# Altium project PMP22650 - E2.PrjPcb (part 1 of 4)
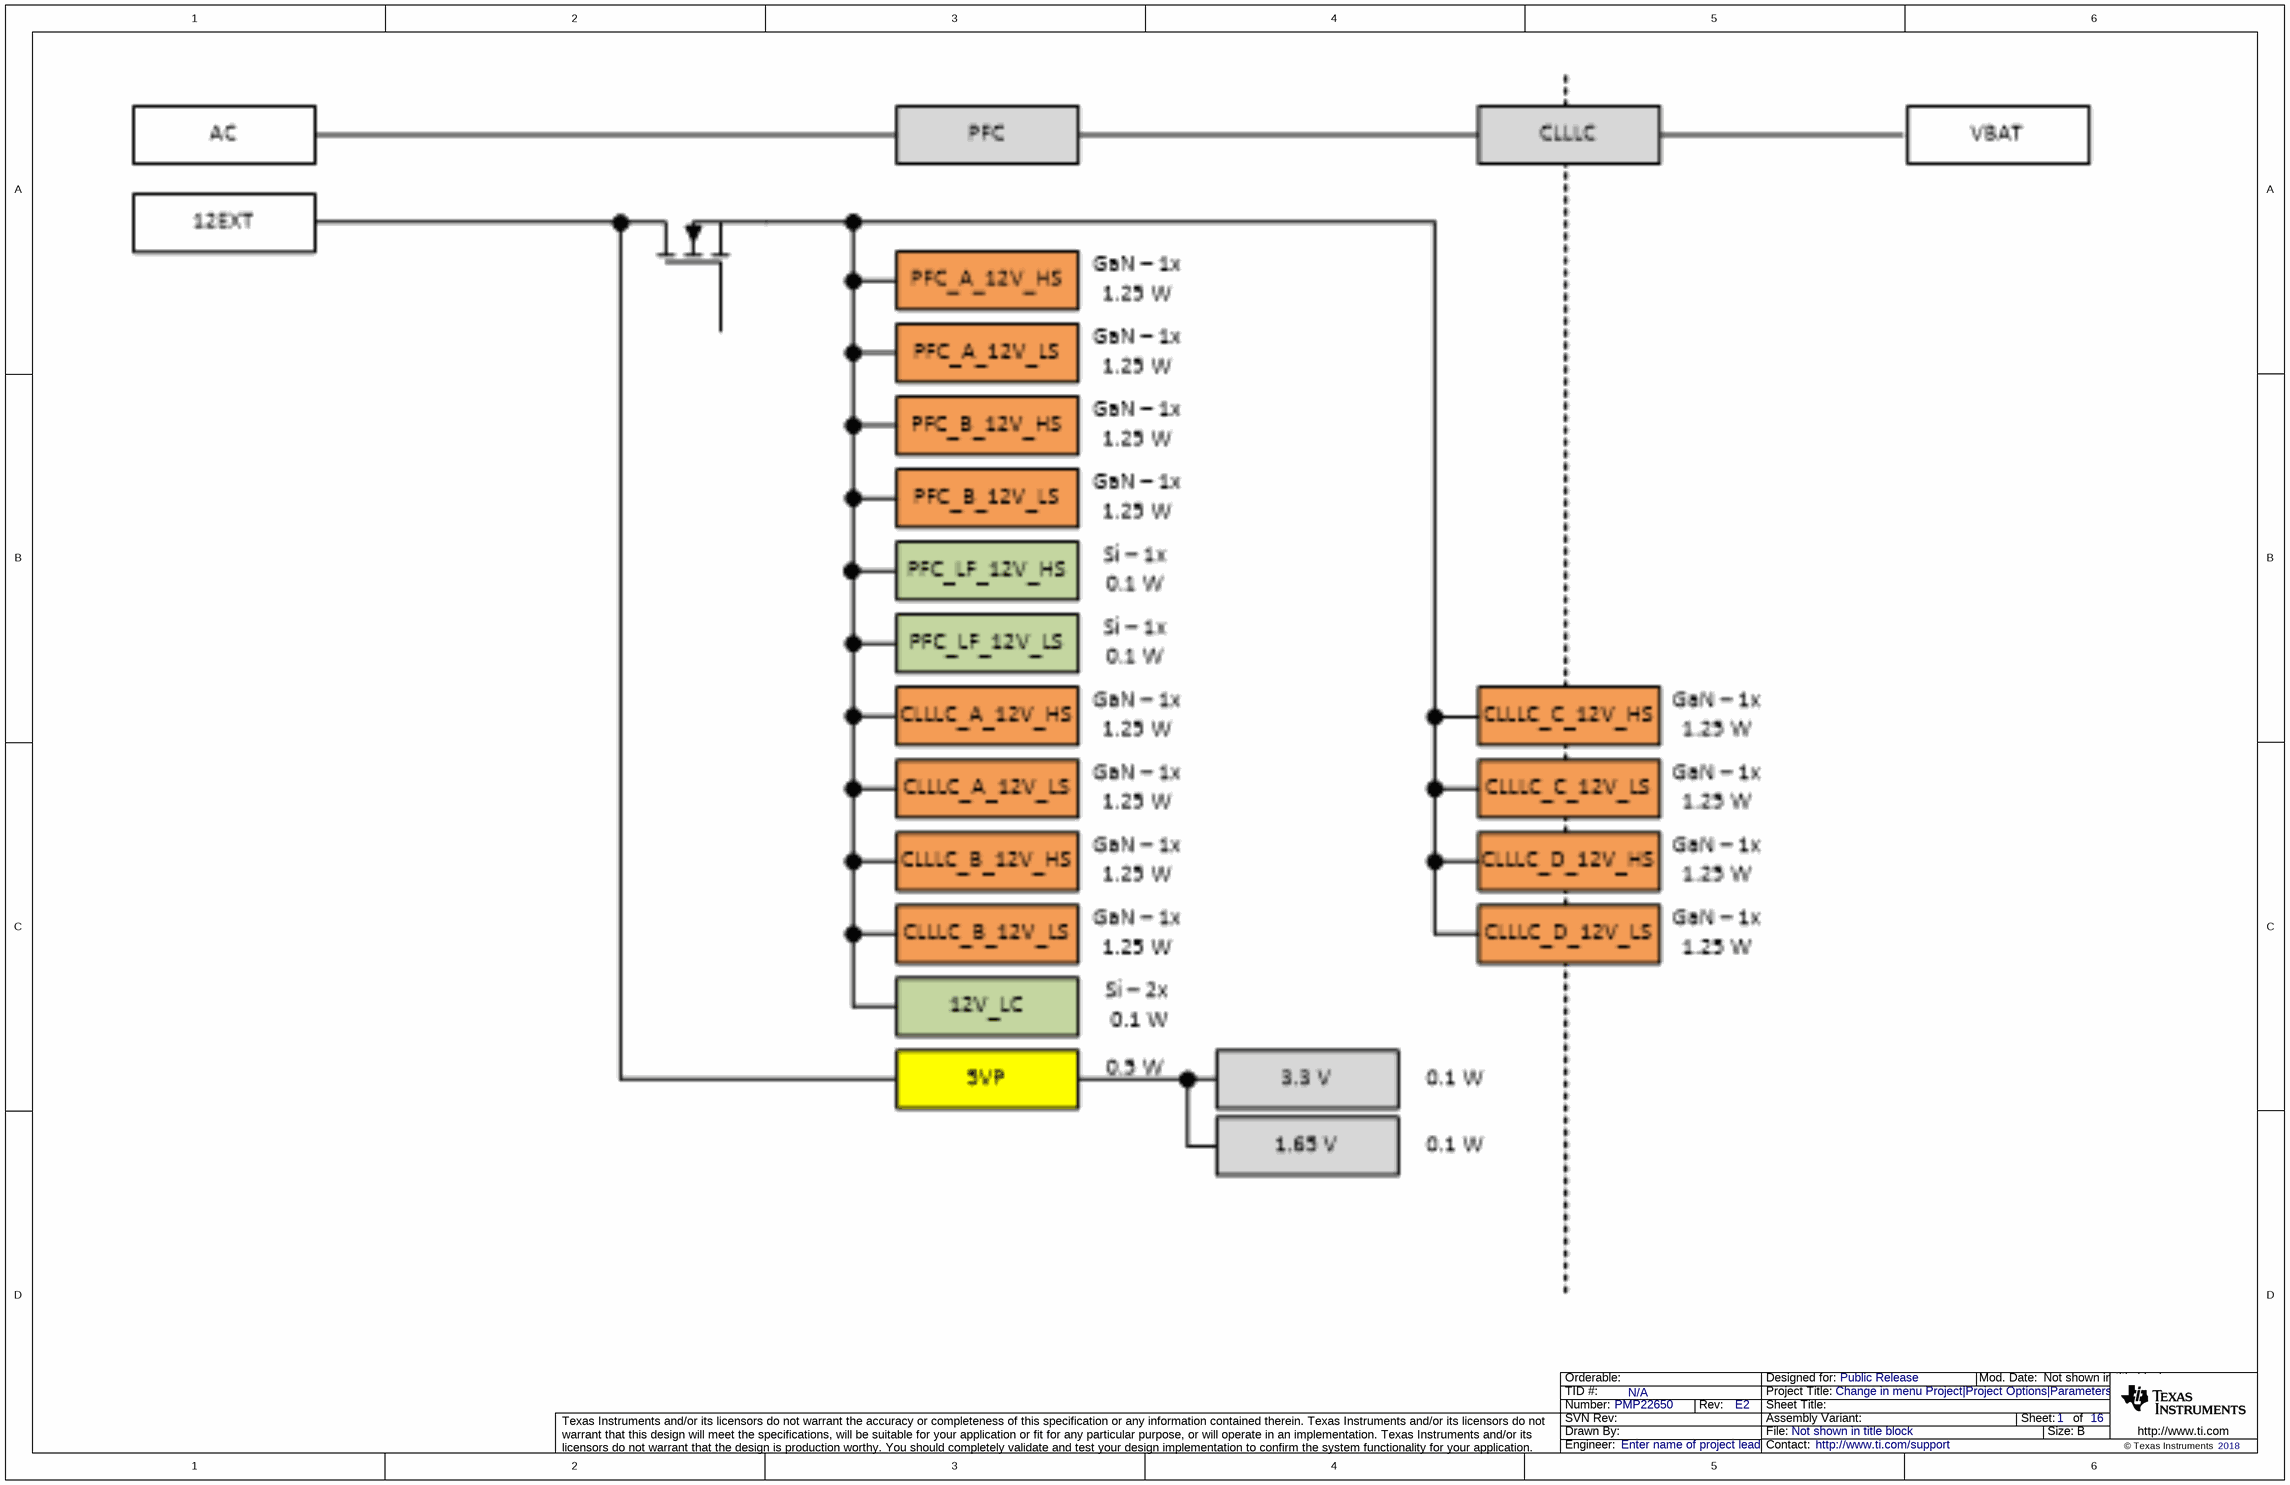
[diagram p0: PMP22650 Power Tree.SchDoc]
CopyrightYear: 2018; PCB_Layout: Who did the Layout?; PCB_Rev: E2; PRJ_Customer: Public Release; PRJ_Engineer: Enter name of project lead; PRJ_Number: PMP22650; PRJ_Title: Change in menu Project|Project Options|Parameters; SCH_Rev: E2; TechSupport: http://www.ti.com/support; TID: N/A
16 sheets, 634 parts. Net scope: global (net labels, ports and power ports of the same name join across sheets).
Board file: PMP22650 PCB.PcbDoc
Sheets:
  PMP22650 Power Tree.SchDoc
  PMP22650 Hardware.SchDoc
  PMP22650 Active EMI.SchDoc
  PMP22650 PFC Power Stage.SchDoc
  PMP22650 PFC GaN PH1.SchDoc
  PMP22650 PFC GaN PH2.SchDoc
  PMP22650 PFC LF FET Gate Driver.SchDoc
  PMP22650 Control.schdoc
  PMP22650 Bias Power and Monitors.SchDoc
  PMP22650 CLLLC Power Stage.SchDoc
  PMP22650 CLLLC GaN Phase A.SchDoc
  PMP22650 CLLLC GaN Phase B.SchDoc
  PMP22650 CLLLC GaN Phase C.SchDoc
  PMP22650 CLLLC GaN Phase D.SchDoc
  PMP22650 CLLLC Primary Sensing.SchDoc
  PMP22650 CLLLC Secondary Sensing.SchDoc

## Sheet PMP22650 Power Tree.SchDoc
size 431 x 279 mm; Date: Not shown in title block; ApprovedBy: Not shown in title block; CheckedBy: Not shown in title block; Author: Not shown in title block; CompanyName: Not shown in title block; Engineer: Not shown in title block; Organization: Not shown in title block; Address1: Not shown in title block; Address2: Not shown in title block; Address3: Not shown in title block; Address4: Not shown in title block; DocumentNumber: 1; Revision: Use project parameter SCH_Rev; SheetNumber: 1; SheetTotal: 16; PageSetup: Record=PageOptions¦CenterHorizontal=True¦CenterVertical=True¦PrintScale=1.00¦XCorrection=1.00¦YCorrection=1.00¦PrintKind=0¦BorderSize=5000000¦LeftOffset=0¦BottomOffset=0¦Orientation=2¦PaperLength=1000¦PaperWidth=1000¦Scale=100¦PaperSource=15¦PrintQuality=600¦MediaType=1¦DitherType=10¦PaperKind=Letter¦PrintScaleMode=1

## Sheet PMP22650 Hardware.SchDoc
size 431 x 279 mm; Date: Not shown in title block; ApprovedBy: Not shown in title block; CheckedBy: Not shown in title block; Author: Not shown in title block; CompanyName: Not shown in title block; Engineer: Not shown in title block; Organization: Not shown in title block; Address1: Not shown in title block; Address2: Not shown in title block; Address3: Not shown in title block; Address4: Not shown in title block; DocumentNumber: 2; Revision: Use project parameter SCH_Rev; SheetNumber: 2; SheetTotal: 16; PageSetup: Record=PageOptions¦CenterHorizontal=True¦CenterVertical=True¦PrintScale=1.00¦XCorrection=1.00¦YCorrection=1.00¦PrintKind=0¦BorderSize=5000000¦LeftOffset=0¦BottomOffset=0¦Orientation=2¦PaperLength=1000¦PaperWidth=1000¦Scale=100¦PaperSource=15¦PrintQuality=600¦MediaType=1¦DitherType=10¦PaperKind=Letter¦PrintScaleMode=1
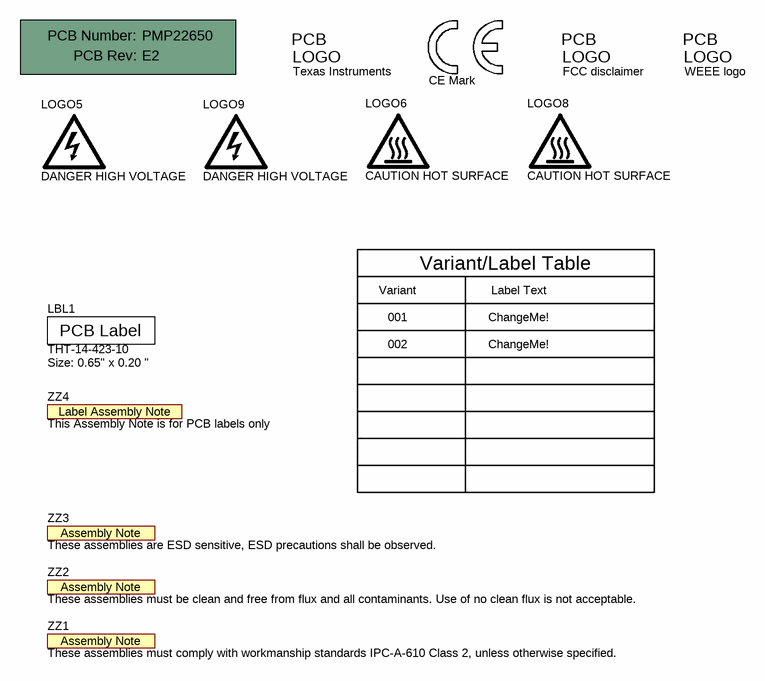
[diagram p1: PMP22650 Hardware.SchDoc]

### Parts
!PCB1  Printed Circuit Board  (value not drawn)  (mechanical)
LBL1  THT-14-423-10  Note: Size: 0.65" x 0.20 "  [Label_650x200]
Logo1  Texas Instruments  [TI_Stacked_Overlay_Small]  (no BOM)
Logo2  FCC disclaimer  [FCC_disclaimer]  (no BOM)
Logo3  WEEE logo  [WEEE_Minimum]  (no BOM)
Logo4  CE Mark  [CE_Mark_5mm]  (no BOM)
LOGO5  DANGER HIGH VOLTAGE  [IEC_HighVoltage_Small]  (no BOM)
LOGO6  CAUTION HOT SURFACE  [IEC_HotSurface_Small]  (no BOM)
LOGO8  CAUTION HOT SURFACE  [IEC_HotSurface_Small]  (no BOM)
LOGO9  DANGER HIGH VOLTAGE  [IEC_HighVoltage_Small]  (no BOM)
ZZ1  These assemblies must comply with workmanship standards IPC-A-610 Class 2, unless otherwise specified.  [AssemblyNote]  (no BOM)
ZZ2  These assemblies must be clean and free from flux and all contaminants. Use of no clean flux is not acceptable.  [AssemblyNote]  (no BOM)
ZZ3  These assemblies are ESD sensitive, ESD precautions shall be observed.  [AssemblyNote]  (no BOM)
ZZ4  This Assembly Note is for PCB labels only  [AssemblyNoteLabel]  (no BOM)

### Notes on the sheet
- Variant
- Variant/Label Table
- Label Text
- 001
- 002
- ChangeMe!

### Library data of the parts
!PCB1 = CMP-0003618-2: Manufacturer: Any; PartNumber: PMP22650
LBL1 = CMP-0003625-1: Thermal Transfer Printable Labels, 0.650" W x 0.200" H - 10,000 per roll; Manufacturer: Brady; CompType: Label
Logo1 = CMP-0074838-1: Texas Instrument Corporate Signature; SymbolCreator: a0412235; Lib Reference: TI_Logo; Library Reference: Logo
Logo2 = CMP-0074847-1: FCC_disclaimer; Library Reference: Logo
Logo3 = CMP-0074769-1
Logo4 = CMP-0074844-1: SymbolCreator: a0412235
LOGO5 LOGO9 = CMP-0074835-1: IEC 61010-1 High Voltage Warning; SymbolCreator: a0412235
LOGO6 LOGO8 = CMP-0074837-1: IEC 61010-1 Hot Surface Warning; SymbolCreator: a0412235
ZZ1 = CMP-0077238-1
ZZ2 = CMP-0077237-1
ZZ3 = CMP-0077236-1
ZZ4 = CMP-0003616-3

## Sheet PMP22650 Active EMI.SchDoc
size 431 x 279 mm; Date: Not shown in title block; ApprovedBy: Not shown in title block; CheckedBy: Not shown in title block; Author: Not shown in title block; CompanyName: Not shown in title block; Engineer: Not shown in title block; Organization: Not shown in title block; Address1: Not shown in title block; Address2: Not shown in title block; Address3: Not shown in title block; Address4: Not shown in title block; DocumentNumber: 3; Revision: Use project parameter SCH_Rev; SheetNumber: 3; SheetTotal: 16; PageSetup: Record=PageOptions¦CenterHorizontal=True¦CenterVertical=True¦PrintScale=1.00¦XCorrection=1.00¦YCorrection=1.00¦PrintKind=0¦BorderSize=5000000¦LeftOffset=0¦BottomOffset=0¦Orientation=2¦PaperLength=1000¦PaperWidth=1000¦Scale=100¦PaperSource=15¦PrintQuality=600¦MediaType=1¦DitherType=10¦PaperKind=Letter¦PrintScaleMode=1
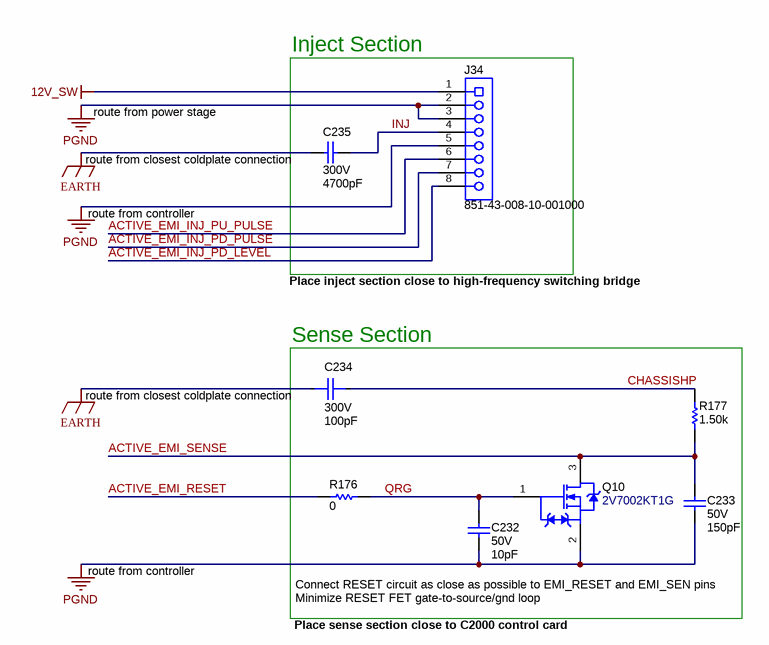
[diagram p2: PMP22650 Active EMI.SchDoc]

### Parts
C232  VDC_V: 50V  ValueDisplayed: 10pF  [0402]  (hidden comment: CGA2B2C0G1H100D050BA)
C233  VDC_V: 50V  ValueDisplayed: 150pF  [0402]  (hidden comment: CGA2B2C0G1H151J050BA)
C234  VAC_Y: 300V  ValueDisplayed: 100pF  [FP-AY2101K29Y5SS63L7_RADIAL-MFG]  (hidden comment: AY2101K29Y5SS63L7)
C235  VDC_V: 300V  ValueDisplayed: 4700pF  [AY2_1300x500_Straight]  (hidden comment: AY2472M49Y5US63L7)
J34  851-43-008-10-001000  [Mill-Max_851-43-008-10-001000]
Q10  2V7002KT1G  [SOT-23]
R176  ValueDisplayed: 0  [0402]  (hidden comment: CRCW04020000Z0ED)
R177  ValueDisplayed: 1.50k  [0402]  (hidden comment: CRCW04021K50FKED)

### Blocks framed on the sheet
Inject Section: C235 J34
Sense Section: C232-C234 Q10 R176 R177

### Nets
12V_SW: J34.1
EARTH: C234.1 C235.2
PGND: C232.2 C233.2 J34.2 J34.3 J34.5 Q10.2(S)
ACTIVE_EMI_INJ_PD_LEVEL: J34.8
ACTIVE_EMI_INJ_PD_PULSE: J34.7
ACTIVE_EMI_INJ_PU_PULSE: J34.6
ACTIVE_EMI_RESET: R176.2
ACTIVE_EMI_SENSE: C233.1 Q10.3(D) R177.1
CHASSISHP: C234.2 R177.2
INJ: C235.1 J34.4
QRG: C232.1 Q10.1(G) R176.1

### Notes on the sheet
- route from power stage
- route from controller
- (near C235) route from closest coldplate connection
- Place inject section close to high-frequency switching bridge
- (near C234) route from closest coldplate connection
- Minimize RESET FET gate-to-source/gnd loop
- Place sense section close to C2000 control card
- Connect RESET circuit as close as possible to EMI_RESET and EMI_SEN pins

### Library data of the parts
C232 = CMP-0006307-2: CAP, CERM, 10 pF, 50 V, +/- 5%, C0G/NP0, AEC-Q200 Grade 1, 0402; Manufacturer: TDK; TaMin_C: -55°C; Polarized: N; SizeAreaWB_mm2: 3; Value1: Unknown; U/M: EA; Value: 10pF; TaMax_C: 125°C; SizeZ_mm: 0.6; SizeX_mm: 1; SizeY_mm: 0.5; AEC Qualified: Y; AEC Category: Q200
C233 = CMP-0006310-2: CAP, CERM, 150 pF, 50 V, +/- 5%, C0G/NP0, AEC-Q200 Grade 1, 0402; Manufacturer: TDK; TaMin_C: -55°C; Polarized: N; SizeAreaWB_mm2: 3; Value1: Unknown; U/M: EA; Value: 150pF; TaMax_C: 125°C; SizeZ_mm: 0.6; SizeX_mm: 1; SizeY_mm: 0.5; AEC Qualified: Y; AEC Category: Q200
C234 = CMP-0090605-2: 100pF ±10% 440VAC Ceramic Capacitor Y5S Radial, Disc; Manufacturer: Vishay; VAC_X: 440V; VDC_V: 1kV; SizeZ_mm: 16mm; AEC Category: Q200; AEC Grade: Grade 1; Voltage Ac Rating X: X1; Voltage Ac Rating Y: Y2; AEC Qualified: Yes
C235 = CMP-0009589-2: CAP, CERM, 4700 pF, 300 V, +/- 20%, Y5U, AEC-Q200 Grade 1, D13xT5mm; Manufacturer: Vishay-Bccomponents; TaMin_C: -55°C; Polarized: N; SizeAreaWB_mm2: 105; Value1: Unknown; U/M: EA; Value: 4700pF; TaMax_C: 125°C; SizeZ_mm: 18; SizeX_mm: 13; SizeY_mm: 5; Cap_Case: 13x5mm; SizeArea_mm2: 65; CompType: Capacitor; AEC Qualified: Y; Cap_F: 4.7nF; AEC Grade: 1; AEC Category: Q200
J34 = CMP-0055072-1: Female Connector, 8x1, 1.27 mm, Black, Tin, TH; Manufacturer: Mill-Max; CT: TRUE; CompType: Socket Strip; CNHeader: FALSE
Q10 = CMP-0000777-1: MOSFET, N-CH, 60 V, 0.32 A, AEC-Q101, SOT-23; Alternate Manufacturer: None; Manufacturer: ON Semiconductor; SizeZ_mm: 1.1; ChType: N; Value2: 0.7 nC; Value1: 2; VdsMax_V: 60V; SizeX_mm: 2.5; SizeY_mm: 3; Vgs_V: 20V; AEC Qualified: Y; Value: 60V; SizeArea_mm2: 7.5; AEC Category: Q101; IdsMax_A: 320mA; SizeAreaWB_mm2: 14; U/M: EA; QgTyp_nC: 0.7
R176 = CMP-0026822-3: RES, 0, 5%, 0.063 W, AEC-Q200 Grade 0, 0402; Manufacturer: Vishay-Dale; Power_W: 63mW; TempCo: 200 ppm/C; Value_Code: 0000; Value: 0; EIA_Code: E24; SizeX_mm: 1; SizeY_mm: 0.5; SizeZ_mm: 0.6; Value2: 0.063W; AEC Qualified: Y; VDC_V: 50V; AEC Category: Q200
R177 = CMP-0026088-3: RES, 1.50 k, 1%, 0.063 W, AEC-Q200 Grade 0, 0402; Manufacturer: Vishay-Dale; Power_W: 63mW; TempCo: 100 ppm/C; Value_Code: 1k50; Value: 1.50k; EIA_Code: E96; Res_ohm: 1.5k; SizeX_mm: 1; SizeY_mm: 0.5; SizeZ_mm: 0.6; Value2: 0.063W; AEC Qualified: Y; VDC_V: 50V; AEC Category: Q200; AEC Grade: 0

## Sheet PMP22650 PFC Power Stage.SchDoc
size 431 x 279 mm; Date: Not shown in title block; ApprovedBy: Not shown in title block; CheckedBy: Not shown in title block; Author: Not shown in title block; CompanyName: Not shown in title block; DrawnBy: G Wang; Engineer: Not shown in title block; Organization: Not shown in title block; Address1: Not shown in title block; Address2: Not shown in title block; Address3: Not shown in title block; Address4: Not shown in title block; DocumentNumber: 4; Revision: Use project parameter SCH_Rev; SheetNumber: 4; SheetTotal: 16; PageSetup: Record=PageOptions¦CenterHorizontal=True¦CenterVertical=True¦PrintScale=1.00¦XCorrection=1.00¦YCorrection=1.00¦PrintKind=0¦BorderSize=5000000¦LeftOffset=0¦BottomOffset=0¦Orientation=2¦PaperLength=1000¦PaperWidth=1000¦Scale=100¦PaperSource=15¦PrintQuality=600¦MediaType=1¦DitherType=10¦PaperKind=Letter¦PrintScaleMode=1
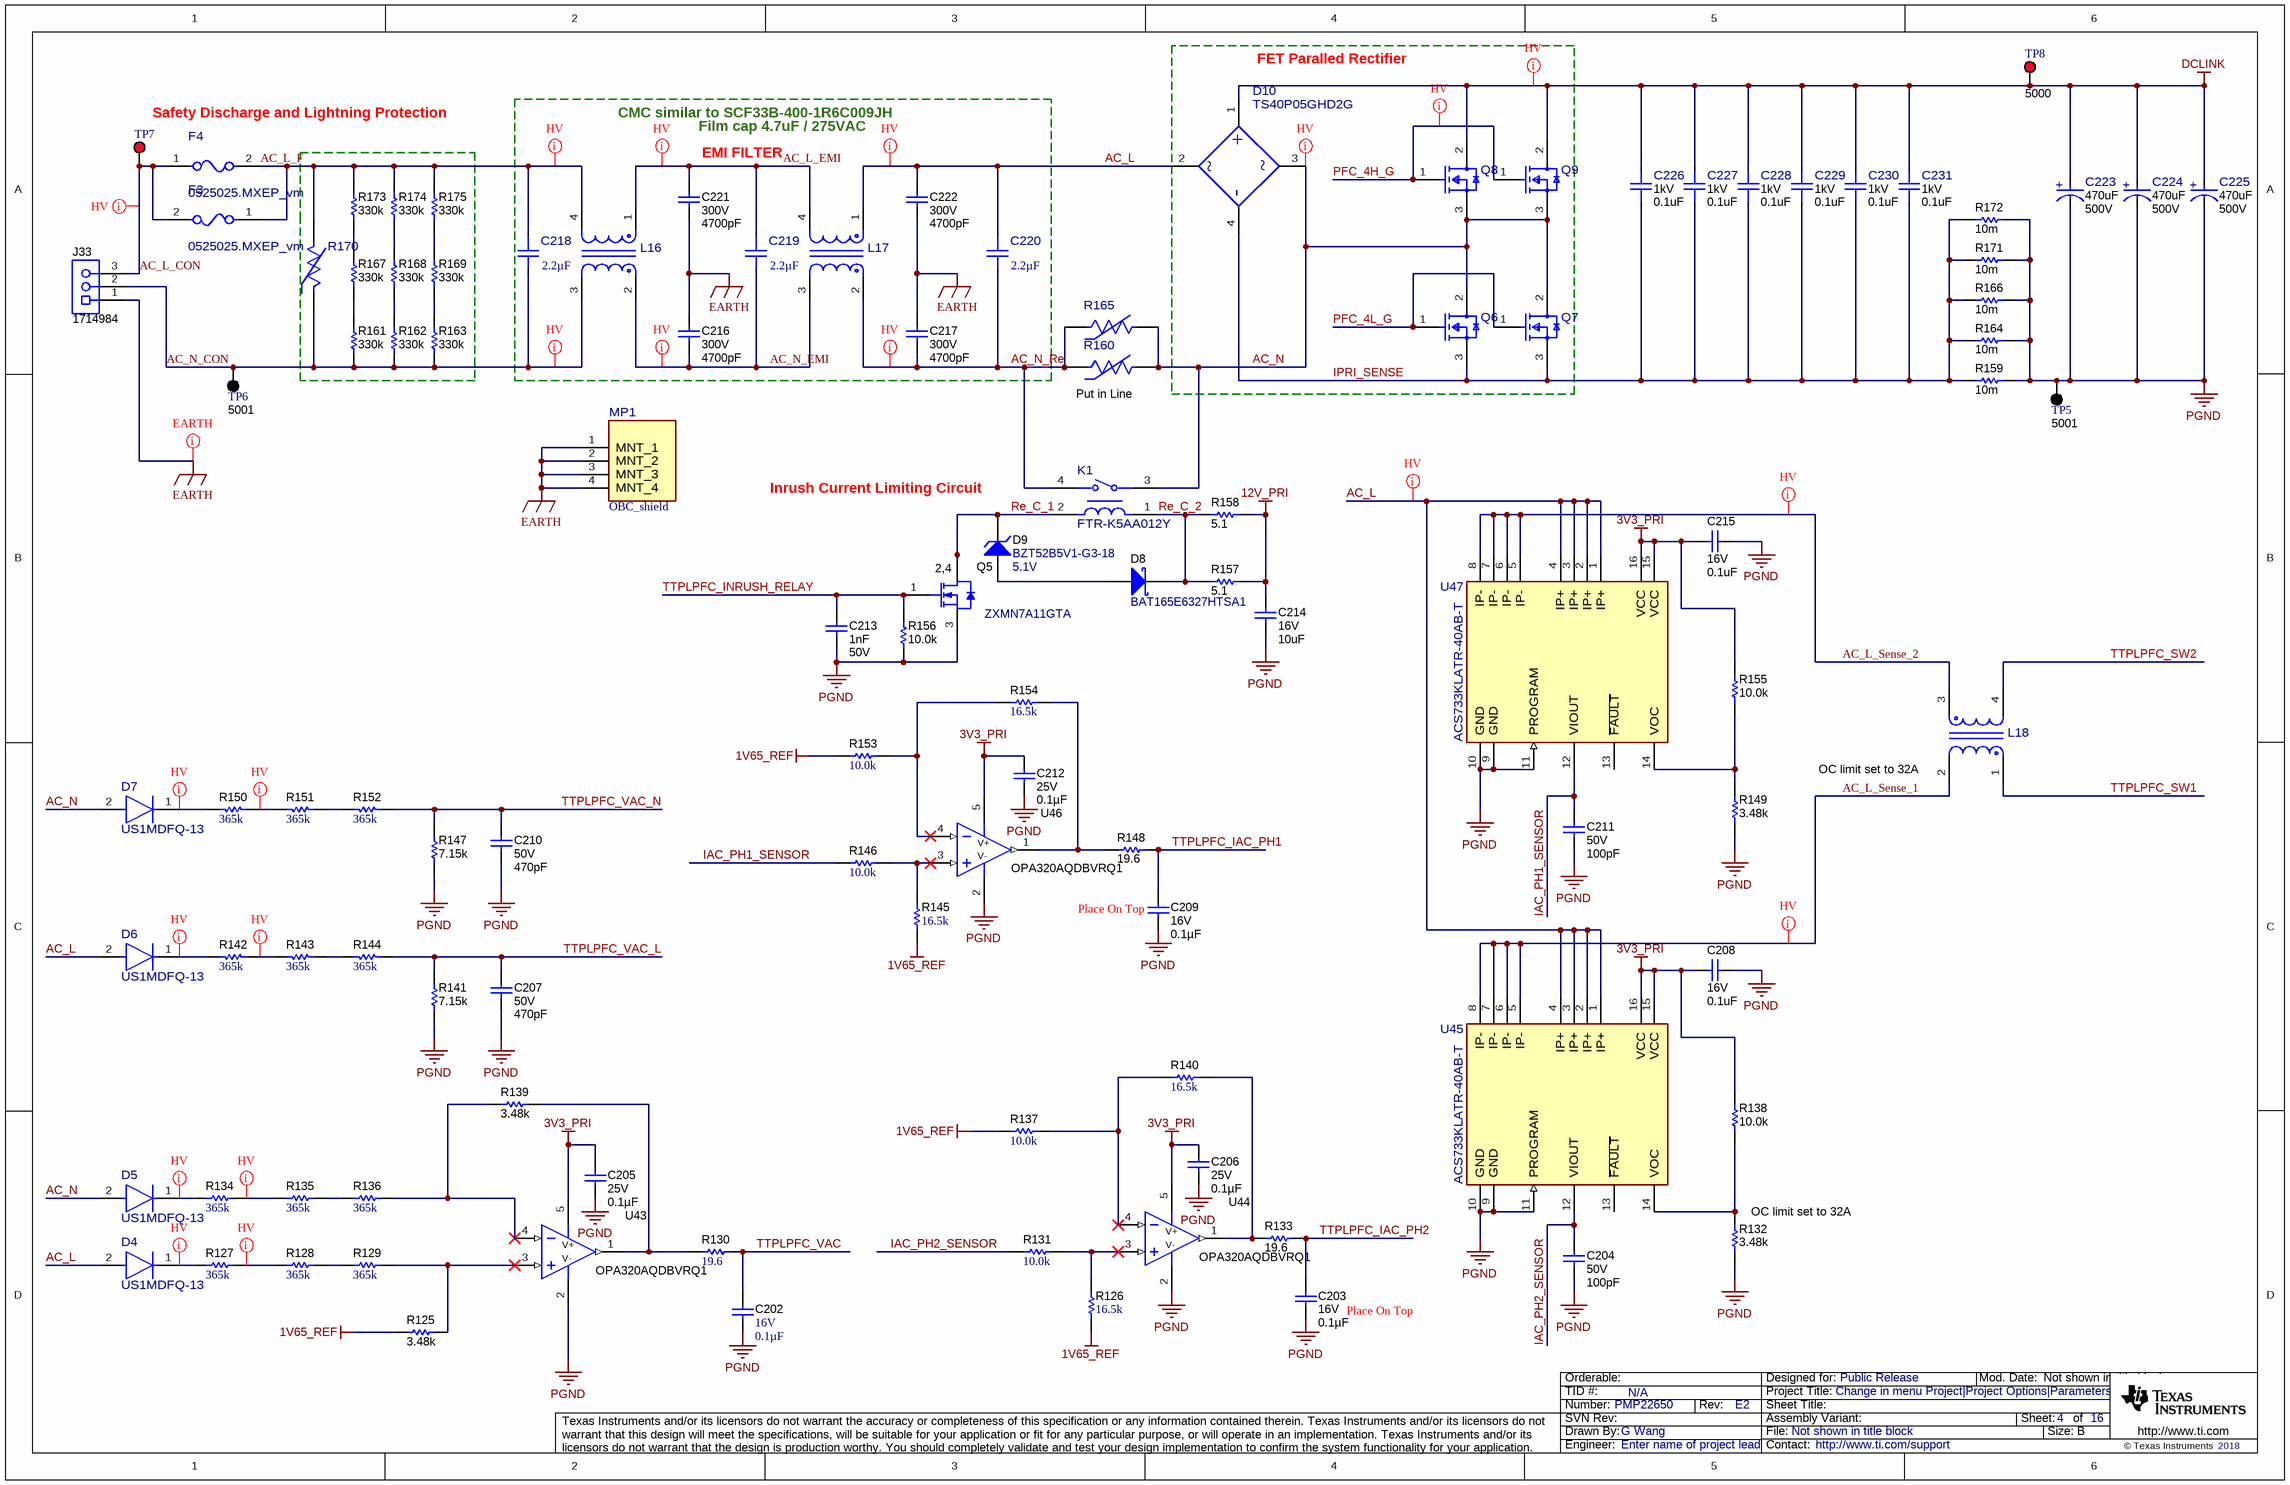
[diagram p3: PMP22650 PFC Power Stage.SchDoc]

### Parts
C202  VDC_V: 16V  ValueDisplayed: 0.1µF  [0402]  (hidden comment: GCM155R71C104JA55D)
C203  VDC_V: 16V  ValueDisplayed: 0.1µF  [0402]  (hidden comment: GCM155R71C104JA55D)
C204  VDC_V: 50V  ValueDisplayed: 100pF  [0402]  (hidden comment: CGA2B2C0G1H101J050BA)
C205  VDC_V: 25V  ValueDisplayed: 0.1µF  [0402]  (hidden comment: CGA2B3X7R1E104K050BB)
C206  VDC_V: 25V  ValueDisplayed: 0.1µF  [0402]  (hidden comment: CGA2B3X7R1E104K050BB)
C207  VDC_V: 50V  ValueDisplayed: 470pF  [0603]  (hidden comment: GCM1885C1H471JA16D)
C208  VDC_V: 16V  ValueDisplayed: 0.1uF  [0402]  (hidden comment: C0402C104K4RACAUTO)
C209  VDC_V: 16V  ValueDisplayed: 0.1µF  [0402]  (hidden comment: GCM155R71C104JA55D)
C210  VDC_V: 50V  ValueDisplayed: 470pF  [0603]  (hidden comment: GCM1885C1H471JA16D)
C211  VDC_V: 50V  ValueDisplayed: 100pF  [0402]  (hidden comment: CGA2B2C0G1H101J050BA)
C212  VDC_V: 25V  ValueDisplayed: 0.1µF  [0402]  (hidden comment: CGA2B3X7R1E104K050BB)
C213  Cap_F: 1nF  VDC_V: 50V  [0603]  (hidden comment: C0603C102J5RACAUTO)
C214  VDC_V: 16V  ValueDisplayed: 10uF  [0805_HV]  (hidden comment: CGA4J1X7S1C106K125AC)
C215  VDC_V: 16V  ValueDisplayed: 0.1uF  [0402]  (hidden comment: C0402C104K4RACAUTO)
C216  VDC_V: 300V  ValueDisplayed: 4700pF  [AY2_1300x500_Straight]  (hidden comment: AY2472M49Y5US63L7)
C217  VDC_V: 300V  ValueDisplayed: 4700pF  [AY2_1300x500_Straight]  (hidden comment: AY2472M49Y5US63L7)
C218  value 2.2µF  [FP-B32923H3225M000_RADIAL-MFG]  (hidden comment: B32923H3225M000)
C219  value 2.2µF  [FP-B32923H3225M000_RADIAL-MFG]  (hidden comment: B32923H3225M000)
C220  value 2.2µF  [FP-B32923H3225M000_RADIAL-MFG]  (hidden comment: B32923H3225M000)
C221  VDC_V: 300V  ValueDisplayed: 4700pF  [AY2_1300x500_Straight]  (hidden comment: AY2472M49Y5US63L7)
C222  VDC_V: 300V  ValueDisplayed: 4700pF  [AY2_1300x500_Straight]  (hidden comment: AY2472M49Y5US63L7)
C223  ValueDisplayed: 470uF  VDC_V: 500V  [FP-ALA7DA471DE500_RADIAL-MFG]  (hidden comment: ALA7DA471DE500)
C224  ValueDisplayed: 470uF  VDC_V: 500V  [FP-ALA7DA471DE500_RADIAL-MFG]  (hidden comment: ALA7DA471DE500)
C225  ValueDisplayed: 470uF  VDC_V: 500V  [FP-ALA7DA471DE500_RADIAL-MFG]  (hidden comment: ALA7DA471DE500)
C226  VDC_V: 1kV  ValueDisplayed: 0.1uF  [FP-C1812X104KDRACAUTO_1812-MFG]  (hidden comment: C1812X104KDRACAUTO)
C227  VDC_V: 1kV  ValueDisplayed: 0.1uF  [FP-C1812X104KDRACAUTO_1812-MFG]  (hidden comment: C1812X104KDRACAUTO)
C228  VDC_V: 1kV  ValueDisplayed: 0.1uF  [FP-C1812X104KDRACAUTO_1812-MFG]  (hidden comment: C1812X104KDRACAUTO)
C229  VDC_V: 1kV  ValueDisplayed: 0.1uF  [FP-C1812X104KDRACAUTO_1812-MFG]  (hidden comment: C1812X104KDRACAUTO)
C230  VDC_V: 1kV  ValueDisplayed: 0.1uF  [FP-C1812X104KDRACAUTO_1812-MFG]  (hidden comment: C1812X104KDRACAUTO)
C231  VDC_V: 1kV  ValueDisplayed: 0.1uF  [FP-C1812X104KDRACAUTO_1812-MFG]  (hidden comment: C1812X104KDRACAUTO)
D4  US1MDFQ-13  [FP-US1MDFQ-13_D-FLAT-MFG]
D5  US1MDFQ-13  [FP-US1MDFQ-13_D-FLAT-MFG]
D6  US1MDFQ-13  [FP-US1MDFQ-13_D-FLAT-MFG]
D7  US1MDFQ-13  [FP-US1MDFQ-13_D-FLAT-MFG]
D8  BAT165E6327HTSA1  [SOD-323]
D9  BZT52B5V1-G3-18  value 5.1V  [SOD-123]
D10  TS40P05GHD2G  [FP-TS40P05GHD2G_SIP4-MFG]
F3  0525025.MXEP_vm  [FP-0525025.MXEP_vm_AXIAL-MFG]
F4  0525025.MXEP_vm  [FP-0525025.MXEP_vm_AXIAL-MFG]
J33  1714984  [Phoenix_1714984]
K1  FTR-K5AA012Y  [FP-FTR-K5AA012Y_RELAY_PTH-MFG]
L16  FRM-DOC-15  [FP-FRM-DOC-15_Common_Mode_Choke_1INCH90_1INCH9-MFG]  (value not drawn)
L17  FRM-DOC-15  [FP-FRM-DOC-15_Common_Mode_Choke_1INCH90_1INCH9-MFG]  (value not drawn)
L18  VI-20174A  [FP-VI-20174A_RADIAL-MFG]  (value not drawn)
MP1  OBC_shield  [0-MFG]
Q5  ZXMN7A11GTA  [SOT-223]
Q6  NVHL025N65S3  [FP-NVHL025N65S3_hm_TO-247-3-MFG]  (value not drawn)
Q7  NVHL025N65S3  [FP-NVHL025N65S3_hm_TO-247-3-MFG]  (value not drawn)
Q8  NVHL025N65S3  [FP-NVHL025N65S3_hm_TO-247-3-MFG]  (value not drawn)
Q9  NVHL025N65S3  [FP-NVHL025N65S3_hm_TO-247-3-MFG]  (value not drawn)
R125  ValueDisplayed: 3.48k  [0603]  (hidden comment: CRCW06033K48FKEA)
R126  ValueDisplayed: 16.5k  [0402]  (hidden comment: CRCW040216K5FKED)
R127  ValueDisplayed: 365k  [1206]  (hidden comment: CRCW1206365KFKEA)
R128  ValueDisplayed: 365k  [1206]  (hidden comment: CRCW1206365KFKEA)
R129  ValueDisplayed: 365k  [1206]  (hidden comment: CRCW1206365KFKEA)
R130  ValueDisplayed: 19.6  [0402]  (hidden comment: CRCW040219R6FKED)
R131  ValueDisplayed: 10.0k  [0402]  (hidden comment: CRCW040210K0FKED)
R132  ValueDisplayed: 3.48k  [0402]  (hidden comment: CRCW04023K48FKED)
R133  ValueDisplayed: 19.6  [0402]  (hidden comment: CRCW040219R6FKED)
R134  ValueDisplayed: 365k  [1206]  (hidden comment: CRCW1206365KFKEA)
R135  ValueDisplayed: 365k  [1206]  (hidden comment: CRCW1206365KFKEA)
R136  ValueDisplayed: 365k  [1206]  (hidden comment: CRCW1206365KFKEA)
R137  ValueDisplayed: 10.0k  [0402]  (hidden comment: CRCW040210K0FKED)
R138  ValueDisplayed: 10.0k  [0402]  (hidden comment: CRCW040210K0FKED)
R139  ValueDisplayed: 3.48k  [0603]  (hidden comment: CRCW06033K48FKEA)
R140  ValueDisplayed: 16.5k  [0402]  (hidden comment: CRCW040216K5FKED)
R141  ValueDisplayed: 7.15k  [0603]  (hidden comment: CRCW06037K15FKEA)
R142  ValueDisplayed: 365k  [1206]  (hidden comment: CRCW1206365KFKEA)
R143  ValueDisplayed: 365k  [1206]  (hidden comment: CRCW1206365KFKEA)
R144  ValueDisplayed: 365k  [1206]  (hidden comment: CRCW1206365KFKEA)
R145  ValueDisplayed: 16.5k  [0402]  (hidden comment: CRCW040216K5FKED)
R146  ValueDisplayed: 10.0k  [0402]  (hidden comment: CRCW040210K0FKED)
R147  ValueDisplayed: 7.15k  [0603]  (hidden comment: CRCW06037K15FKEA)
R148  ValueDisplayed: 19.6  [0402]  (hidden comment: CRCW040219R6FKED)
R149  ValueDisplayed: 3.48k  [0402]  (hidden comment: CRCW04023K48FKED)
R150  ValueDisplayed: 365k  [1206]  (hidden comment: CRCW1206365KFKEA)
R151  ValueDisplayed: 365k  [1206]  (hidden comment: CRCW1206365KFKEA)
R152  ValueDisplayed: 365k  [1206]  (hidden comment: CRCW1206365KFKEA)
R153  ValueDisplayed: 10.0k  [0402]  (hidden comment: CRCW040210K0FKED)
R154  ValueDisplayed: 16.5k  [0402]  (hidden comment: CRCW040216K5FKED)
R155  ValueDisplayed: 10.0k  [0402]  (hidden comment: CRCW040210K0FKED)
R156  ValueDisplayed: 10.0k  [0603]  (hidden comment: CRCW060310K0FKEA)
R157  ValueDisplayed: 5.1  [1206]  (hidden comment: CRCW12065R10JNEA)
R158  ValueDisplayed: 5.1  [1206]  (hidden comment: CRCW12065R10JNEA)
R159  ValueDisplayed: 10m  [FP-CRF1206-FZ-R010ELF_1206-MFG]  (hidden comment: CRF1206-FZ-R010ELF)
R160  B59101P1080A062  [FP-B59101P1080A062_SMD2-MFG]  (value not drawn)
R161  ValueDisplayed: 330k  [1206]  (hidden comment: CRCW1206330KJNEA)
R162  ValueDisplayed: 330k  [1206]  (hidden comment: CRCW1206330KJNEA)
R163  ValueDisplayed: 330k  [1206]  (hidden comment: CRCW1206330KJNEA)
R164  ValueDisplayed: 10m  [FP-CRF1206-FZ-R010ELF_1206-MFG]  (hidden comment: CRF1206-FZ-R010ELF)
R165  B59101P1080A062  [FP-B59101P1080A062_SMD2-MFG]  (value not drawn)
R166  ValueDisplayed: 10m  [FP-CRF1206-FZ-R010ELF_1206-MFG]  (hidden comment: CRF1206-FZ-R010ELF)
R167  ValueDisplayed: 330k  [1206]  (hidden comment: CRCW1206330KJNEA)
R168  ValueDisplayed: 330k  [1206]  (hidden comment: CRCW1206330KJNEA)
R169  ValueDisplayed: 330k  [1206]  (hidden comment: CRCW1206330KJNEA)
R170  V20H510AUTO  [FP-V20H510AUTO_RADIAL-MFG]  (value not drawn)
R171  ValueDisplayed: 10m  [FP-CRF1206-FZ-R010ELF_1206-MFG]  (hidden comment: CRF1206-FZ-R010ELF)
R172  ValueDisplayed: 10m  [FP-CRF1206-FZ-R010ELF_1206-MFG]  (hidden comment: CRF1206-FZ-R010ELF)
R173  ValueDisplayed: 330k  [1206]  (hidden comment: CRCW1206330KJNEA)
R174  ValueDisplayed: 330k  [1206]  (hidden comment: CRCW1206330KJNEA)
R175  ValueDisplayed: 330k  [1206]  (hidden comment: CRCW1206330KJNEA)
TP5  5001  [Keystone5001]
TP6  5001  [Keystone5001]
TP7  5000  [Keystone5000]  (value not drawn)
TP8  5000  [Keystone5000]
U43  OPA320AQDBVRQ1  [DBV0005A_N]
U44  OPA320AQDBVRQ1  [DBV0005A_N]
U45  ACS733KLATR-40AB-T  [FP-ACS733KLATR-40AB-T_SOIC16-MFG]
U46  OPA320AQDBVRQ1  [DBV0005A_N]
U47  ACS733KLATR-40AB-T  [FP-ACS733KLATR-40AB-T_SOIC16-MFG]

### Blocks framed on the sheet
FET Paralled Rectifier: D10 Q6-Q9

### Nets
1V65_REF: R125.1 R126.1 R137.1 R145.2 R153.1
3V3_PRI: C205.1 C206.1 C208.2 C212.1 C215.2 R138.2 R155.2 U43.5(V+) U44.5(V+) U45.15(VCC) U45.16(VCC) U46.5(V+) U47.15(VCC) U47.16(VCC)
12V_PRI: C214.1 R157.2 R158.2
DCLINK: C223.2(ANODE) C224.2(ANODE) C225.2(ANODE) C226.2 C227.2 C228.2 C229.2 C230.2 C231.2 D10.1(+) Q8.2(D) Q9.2(D) TP8.1
EARTH: C216.2 C217.2 C221.1 C222.1 J33.1 MP1.1(MNT_1) MP1.2(MNT_2) MP1.3(MNT_3) MP1.4(MNT_4)
PGND: C202.2 C203.2 C204.2 C205.2 C206.2 C207.2 C208.1 C209.2 C210.2 C211.2 C212.2 C213.2 C214.2 C215.1 C223.1(CATHODE) C224.1(CATHODE) C225.1(CATHODE) Q5.3(S) R132.1 R141.2 R147.2 R149.1 R156.1 R159.2 R164.2 R166.2 R171.2 R172.2 TP5.1 U43.2(V-) U44.2(V-) U45.9(GND) U45.10(GND) U45.11(PROGRAM) U46.2(V-) U47.9(GND) U47.10(GND) U47.11(PROGRAM)
AC_L: C220.1 C222.2 D4.2(ANODE) D6.2(ANODE) D10.2(1_~) L17.1 U45.1(IP+) U45.2(IP+) U45.3(IP+) U45.4(IP+) U47.1(IP+) U47.2(IP+) U47.3(IP+) U47.4(IP+)
AC_L_CON: F3.2 F4.1 J33.3 TP7.1
AC_L_EMI: C219.1 C221.2 L16.1 L17.4
AC_L_F: C218.1 F3.1 F4.2 L16.4 R170.1 R173.2 R174.2 R175.2
AC_L_Sense_1: L18.2 U45.5(IP-) U45.6(IP-) U45.7(IP-) U45.8(IP-)
AC_L_Sense_2: L18.3 U47.5(IP-) U47.6(IP-) U47.7(IP-) U47.8(IP-)
AC_N: D5.2(ANODE) D7.2(ANODE) D10.3(2_~) K1.3 Q6.2(D) Q7.2(D) Q8.3(S) Q9.3(S) R160.2 R165.2
AC_N_CON: C218.2 J33.2 L16.3 R161.1 R162.1 R163.1 R170.2 TP6.1
AC_N_EMI: C216.1 C219.2 L16.2 L17.3
AC_N_Re: C217.1 C220.2 K1.4 L17.2 R160.1 R165.1
IAC_PH1_SENSOR: C211.1 R146.1 U47.12(VIOUT)
IAC_PH2_SENSOR: C204.1 R131.1 U45.12(VIOUT)
IPRI_SENSE: C226.1 C227.1 C228.1 C229.1 C230.1 C231.1 D10.4(-) Q6.3(S) Q7.3(S) R159.1 R164.1 R166.1 R171.1 R172.1
PFC_4H_G: Q8.1(G) Q9.1(G)
PFC_4L_G: Q6.1(G) Q7.1(G)
Re_C_1: D9.1(K) K1.2 Q5.2(D) Q5.4(D)
Re_C_2: D8.1(K) K1.1 R157.1 R158.1
TTPLPFC_IAC_PH1: C209.1 R148.2
TTPLPFC_IAC_PH2: C203.1 R133.2
TTPLPFC_INRUSH_RELAY: C213.1 Q5.1(G) R156.2
TTPLPFC_SW1: L18.1
TTPLPFC_SW2: L18.4
TTPLPFC_VAC: C202.1 R130.2
TTPLPFC_VAC_L: C207.1 R141.1 R144.1
TTPLPFC_VAC_N: C210.1 R147.1 R152.1
NetD4_1: D4.1(CATHODE) R127.1
NetD5_1: D5.1(CATHODE) R134.1
NetD6_1: D6.1(CATHODE) R142.2
NetD7_1: D7.1(CATHODE) R150.2
NetD8_2: D8.2(A) D9.2(A)
NetR125_2: R125.2 R129.2 U43.3(IN+)
NetR126_2: R126.2 R131.2 U44.3(IN+)
NetR127_2: R127.2 R128.1
NetR128_2: R128.2 R129.1
NetR130_1: R130.1 R139.2 U43.1(OUT)
NetR132_2: R132.2 R138.1 U45.14(VOC)
NetR133_1: R133.1 R140.2 U44.1(OUT)
NetR134_2: R134.2 R135.1
NetR135_2: R135.2 R136.1
NetR136_2: R136.2 R139.1 U43.4(IN-)
NetR137_2: R137.2 R140.1 U44.4(IN-)
NetR142_1: R142.1 R143.2
NetR143_1: R143.1 R144.2
NetR145_1: R145.1 R146.2 U46.3(IN+)
NetR148_1: R148.1 R154.2 U46.1(OUT)
NetR149_2: R149.2 R155.1 U47.14(VOC)
NetR150_1: R150.1 R151.2
NetR151_1: R151.1 R152.2
NetR153_2: R153.2 R154.1 U46.4(IN-)
NetR161_2: R161.2 R167.1
NetR162_2: R162.2 R168.1
NetR163_2: R163.2 R169.1
NetR167_2: R167.2 R173.1
NetR168_2: R168.2 R174.1
NetR169_2: R169.2 R175.1

Not connected (* = marked no-connect by the designer): U45 13(~{FAULT}); U47 13(~{FAULT})

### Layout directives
net class HV: AC_L, AC_L_CON, AC_L_EMI, AC_L_F, AC_L_Sense_1, AC_L_Sense_2, AC_N, AC_N_CON, AC_N_EMI, AC_N_Re, DCLINK, NetD4_1, NetD5_1, NetD6_1, NetD7_1, NetR127_2, NetR134_2, NetR142_1, NetR150_1, PFC_4H_G
net class EARTH: EARTH

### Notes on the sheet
- Safety Discharge and Lightning Protection
- (near C221) EMI FILTER
- CMC similar to SCF33B-400-1R6C009JH
- Film cap 4.7uF / 275VAC
- (near R160) Put in Line
- (near D9) Inrush Current Limiting Circuit
- (near L18) OC limit set to 32A
- (near C209) Place On Top
- (near R132) OC limit set to 32A
- (near C203) Place On Top

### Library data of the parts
C202 = CMP-0080702-1: CAP, CERM, 0.1 µF, 16 V,+/- 5%, X7R, AEC-Q200 Grade 1, 0402; Manufacturer: MuRata; TaMin_C: -55°C; Polarized: N; SizeAreaWB_mm2: 3; U/M: EA; Value: 0.1uF; TaMax_C: 125°C; SizeZ_mm: 0.6; SizeX_mm: 1; SizeY_mm: 0.5; AEC Qualified: Y; Cap_F: 100nF; AEC Category: Q200
C203 C209 = CMP-0080702-1: CAP, CERM, 0.1 µF, 16 V,+/- 5%, X7R, AEC-Q200 Grade 1, 0402; Manufacturer: MuRata; Cap_F: 100nF; SizeAreaWB_mm2: 3; SizeArea_mm2: 0.5; AEC Qualified: Y; AEC Category: Q200; Value: 0.1uF; TaMax_C: 125°C; SizeZ_mm: 0.6; AEC Grade: 1; Polarized: N; TaMin_C: -55°C; U/M: EA
C204 C211 = CMP-0006308-2: CAP, CERM, 100 pF, 50 V, +/- 5%, C0G/NP0, AEC-Q200 Grade 1, 0402; Manufacturer: TDK; TaMin_C: -55°C; Polarized: N; SizeAreaWB_mm2: 3; Value1: Unknown; U/M: EA; Value: 100pF; TaMax_C: 125°C; SizeZ_mm: 0.6; SizeX_mm: 1; SizeY_mm: 0.5; AEC Qualified: Y; AEC Category: Q200
C205 C206 C212 = CMP-0080610-1: CAP, CERM, 0.1 µF, 25 V,+/- 10%, X7R, AEC-Q200 Grade 1, 0402; Manufacturer: TDK; TaMin_C: -55°C; Polarized: N; SizeAreaWB_mm2: 3; U/M: EA; Value: 0.1uF; TaMax_C: 125°C; SizeZ_mm: 0.6; SizeX_mm: 1; SizeY_mm: 0.5; AEC Qualified: Y; Cap_F: 100nF; AEC Category: Q200
C207 C210 = CMP-0007127-4: CAP, CERM, 470 pF, 50 V, +/- 5%, C0G/NP0, AEC-Q200 Grade 1, 0603; Manufacturer: MuRata; TaMin_C: -55°C; Polarized: N; SizeAreaWB_mm2: 4.68; Value1: Unknown; U/M: EA; Value: 470pF; TaMax_C: 125°C; SizeZ_mm: 1; SizeX_mm: 1.6; SizeY_mm: 0.8; SizeArea_mm2: 1.28; AEC Qualified: Y; AEC Category: Q200
C208 C215 = CMP-0006237-2: CAP, CERM, 0.1 uF, 16 V, +/- 10%, X7R, AEC-Q200 Grade 1, 0402; Manufacturer: Kemet; TaMin_C: -55°C; Polarized: N; SizeAreaWB_mm2: 3; Value1: Unknown; U/M: EA; Value: 0.1uF; TaMax_C: 125°C; SizeZ_mm: 0.6; SizeX_mm: 1; SizeY_mm: 0.5; AEC Qualified: Y; Cap_F: 100nF; AEC Category: Q200
C213 = CMP-0006844-4: CAP, CERM, 1000 pF, 50 V, +/- 5%, X7R, AEC-Q200 Grade 1, 0603; Manufacturer: Kemet; TaMin_C: -55°C; Polarized: N; SizeAreaWB_mm2: 4.68; Value1: Unknown; U/M: EA; Value: 1000pF; TaMax_C: 125°C; SizeZ_mm: 1; SizeX_mm: 1.6; SizeY_mm: 0.8; SizeArea_mm2: 1.28; AEC Qualified: Y; AEC Category: Q200
C214 = CMP-0007965-2: CAP, CERM, 10 uF, 16 V, +/- 10%, X7S, AEC-Q200 Grade 1, 0805; Manufacturer: TDK; TaMin_C: -55°C; Polarized: N; SizeAreaWB_mm2: 6.75; Value1: Unknown; U/M: EA; Value: 10uF; TaMax_C: 125°C; SizeZ_mm: 1.45; SizeX_mm: 2; SizeY_mm: 1.25; Cap_Case: 0805; SizeArea_mm2: 2.5; AEC Qualified: Y; Cap_F: 10µF; AEC Grade: 1; AEC Category: Q200
C216 C217 C221 C222 = CMP-0009589-2: as C235 on sheet PMP22650 Active EMI
C218-C220 = CMP-0090606-1: 2.2µF Film Capacitor 305V 630V Polypropylene (PP), Metallized Radial; Manufacturer: TDK; AEC Qualified: Yes; VAC_X: X2; Tolerance_%: 20%; SizeZ_mm: 29.5mm; AEC Grade: Grade 2; ValueDisplayed: 2.2uF
C223-C225 = CMP-0090234-1: 470µF 500V Aluminum Electrolytic Capacitors Radial, Can - Snap-In 532.2mOhm @ 100Hz 15000 Hrs @ 85°C; Manufacturer: Kemet; Leakage Current: 6uA; SizeZ_mm: 47mm; IRMS_A: 4.6A; Life: 15000Hours; Tolerance_%: 20%; AEC Grade: Grade 3; Esr: 0.532; AEC Qualified: Yes
C226-C231 = CMP-0090548-1: 0.1µF ±10% 1000V (1kV) Ceramic Capacitor X7R 1812 (4532 Metric); Manufacturer: Kemet; SizeZ_mm: 1.85mm; AEC Qualified: Yes; Cap_F: 100nF; TempCo: 15%; Value: 100nF; AEC Grade: Grade 1
D4-D7 = CMP-0089095-1: Diode Standard 1000V 1A Surface Mount D-Flat; Manufacturer: Diodes; AEC Qualified: Yes; Vf_V: 1kV; Max Surge Forward Current: 30A; SizeZ_mm: 1.1mm; Peak Reverse Current: 5uA; Cap_F: 10pF; AEC Grade: Grade 0; TJmax_C: 150°C
D8 = CMP-0028882-2: Diode, Schottky, 40 V, 0.75 A, AEC-Q101, SOD-323; Manufacturer: Infineon Technologies; SizeAreaWB_mm2: 8.695; SizeX_mm: 2.7; Value1: 0.75A; Value2: 0.74V; SizeArea_mm2: 3.645; Vr_V: 40V; SizeY_mm: 1.35; Io_A: 750mA; Green_REACh: Incomplete; Value: 40V; Vf_V: 740mV; AEC Qualified: Y; SizeZ_mm: 1; Green_Lifecycle: Not Set; AEC Category: Q101; TJmax_C: 150°C
D9 = CMP-0065110-3: Diode, Zener, 5.1 V, 500 mW, AEC-Q101, SOD-123; Manufacturer: Vishay-Semiconductor; SizeArea_mm2: 6.545; SizeAreaWB_mm2: 13.095; AEC Category: Q101; SizeY_mm: 1.7; Power_W: 500mW; RJA_CperW: 300; SizeZ_mm: 1.35; Value1: 0.5W; AEC Qualified: Y; SizeX_mm: 3.85
D10 = CMP-0090610-1: Bridge Rectifier Single Phase Standard 600V Through Hole TS-6P; Manufacturer: Taiwan Semiconductor; TJmax_C: 150°C; AEC Qualified: Yes; SizeZ_mm: 24.5mm; Forward Current: 40A; Standoff Height: 3.8mm; Max Surge Forward Current: 400A; Peak Reverse Current: 10uA; AEC Grade: Grade 0
F3 F4 = CMP-4956-0000-1: 25A AC 450V DC Fuse Cartridge, Ceramic Through Hole 3AB, 3AG, 1/4" x 1-1/4" (Axial); Manufacturer: Littelfuse; AEC Grade: NA; Fuse Interrupt Dc Current: 10000A; AEC Qualified: No; Res_ohm: 3.8mΩ; MeltingTyp: 320A2Sec; Interrupt_DC: 10kA
J33 = CMP-0055493-1: Terminal Block, 3x1, 9.52MM, TH; Manufacturer: Phoenix Contact; CNHeader: FALSE; Green_Lifecycle: Not Set; Green_REACh: Incomplete; CT: TRUE
K1 = CMP-0090589-1: Relay Automotive SPST-NO 32A 12VDC 160 Ohm Through Hole; Manufacturer: Fujitsu; Switching Current: 40A; Coil Power_W: 440mW; SizeZ_mm: 30mm; Coil Type: Non-Latching; Coil Resistance: 160Ω; TaMax_C: +105°C; Coil Voltage_VDC: 12V; AEC Qualified: Yes; Max Power Dissipation: 900mW; AEC Grade: Grade 2
L16 L17 = CMP-0090759-1: Common Mode Choke; Manufacturer: Renco Electronics; Test Frequency: 10kHz; Ind_H: 1.8mH; AEC Qualified: No; DCR_ohm: 2.6m; SizeZ_mm: 1.9inch
L18 = CMP-0091444-1: Coupled PFC; Manufacturer: Cyntec; Ind_H: 77µH; Test Frequency: 100kHz; AEC Qualified: No; DCR_ohm: 12m; SizeZ_mm: 42.3mm
MP1 = CMP-0090997-2: Shield; Manufacturer: Texas Instruments; Conn Orientation: Vertical; SizeZ_mm: 50mm
Q5 = CMP-0000888-1: MOSFET, N-CH, 70 V, 3.8 A, AEC-Q101, SOT-223; Alternate Manufacturer: None; Manufacturer: Diodes Inc.; SizeZ_mm: 1.6; ChType: N; Value2: 7.4 nC; Value1: 0.1; VdsMax_V: 70V; SizeX_mm: 6.5; SizeY_mm: 7; Vgs_V: 20V; AEC Qualified: Y; Value: 70V; Rdson45_ohm: 0.19; SizeArea_mm2: 45.5; AEC Category: Q101; IdsMax_A: 3.8A; SizeAreaWB_mm2: 76.5; U/M: EA; QgTyp_nC: 7.4
Q6-Q9 = CMP-0090619-2: N-Channel 650V 75A (Tc) 595W (Tc) Through Hole TO-247-3; Manufacturer: ON Semiconductor; Pulse Drain Current: 187.5A; QgTyp_nC: 236nC @ 10V; Threshold Vgs Max: 4.5V; VdsMax_V: 1.2V; Number Of N Channels: 1; Drain To Source Breakdown Voltage: 713V; Rthja Max: 40°C/W; Rdson45_ohm: 19.9m; AEC Grade: Grade 0; Standoff Height: 3.69mm; Threshold Vgs Min: 2.5V; Reverse Recovery Time: 714ns; Transconductance: 78.5S; ChMode: False; TJmax_C: +150°C; Turn Off Delay Time: 120ns; Vgs_V: 30V; SizeZ_mm: 24.75mm; Turn On Delay Time: 43.3ns; AEC Qualified: Yes; Typ Forward Diode Voltage: 0.88V; Reverse Recovery Charge: 26400nC; Input Capacitace At Vds: 7330pF @ 400V
R125 R139 = CMP-0022377-4: RES, 3.48 k, 1%, 0.1 W, AEC-Q200 Grade 0, 0603; Manufacturer: Vishay-Dale; Power_W: 100mW; TempCo: 100 ppm/C; Value_Code: 3k48; Value: 3.48k; EIA_Code: E96; SizeX_mm: 1.6; SizeY_mm: 0.8; SizeZ_mm: 1; Value2: 0.1W; SizeArea_mm2: 1.28; AEC Qualified: Y; VDC_V: 75V; AEC Category: Q200; AEC Grade: 0
R126 R140 R145 R154 = CMP-0026041-3: RES, 16.5 k, 1%, 0.063 W, AEC-Q200 Grade 0, 0402; Manufacturer: Vishay-Dale; Power_W: 63mW; TempCo: 100 ppm/C; Value_Code: 16k5; Value: 16.5k; EIA_Code: E96; SizeX_mm: 1; SizeY_mm: 0.5; SizeZ_mm: 0.6; Value2: 0.063W; AEC Qualified: Y; VDC_V: 50V; AEC Category: Q200; AEC Grade: 0
R127-R129 R134-R136 R142-R144 R150-R152 = CMP-0016927-3: RES, 365 k, 1%, 0.25 W, AEC-Q200 Grade 0, 1206; Manufacturer: Vishay-Dale; Power_W: 250mW; TempCo: 100 ppm/C; Value: 365k; EIA_Code: E96; SizeX_mm: 3.2; SizeY_mm: 1.6; SizeZ_mm: 1.35; Value2: 0.25W; SizeArea_mm2: 5.12; AEC Qualified: Y; VDC_V: 200V; AEC Category: Q200; AEC Grade: 0
R130 R133 R148 = CMP-0026070-3: RES, 19.6, 1%, 0.063 W, AEC-Q200 Grade 0, 0402; Manufacturer: Vishay-Dale; Power_W: 63mW; TempCo: 100 ppm/C; Value_Code: 19R6; Value: 19.6; EIA_Code: E96; SizeX_mm: 1; SizeY_mm: 0.5; SizeZ_mm: 0.6; Value2: 0.063W; AEC Qualified: Y; VDC_V: 50V; AEC Category: Q200; AEC Grade: 0
R131 R137 R138 R146 R153 R155 = CMP-0025958-3: RES, 10.0 k, 1%, 0.063 W, AEC-Q200 Grade 0, 0402; Manufacturer: Vishay-Dale; Power_W: 63mW; TempCo: 100 ppm/C; Value_Code: 10k0; Value: 10.0k; EIA_Code: E96; Res_ohm: 10k; SizeX_mm: 1; SizeY_mm: 0.5; SizeZ_mm: 0.6; Value2: 0.063W; AEC Qualified: Y; VDC_V: 50V; AEC Category: Q200; AEC Grade: 0
R132 R149 = CMP-0026335-2: RES, 3.48 k, 1%, 0.063 W, AEC-Q200 Grade 0, 0402; Manufacturer: Vishay-Dale; Power_W: 63mW; TempCo: 100 ppm/C; Value_Code: 3k48; Value: 3.48k; EIA_Code: E96; SizeX_mm: 1; SizeY_mm: 0.5; SizeZ_mm: 0.6; Value2: 0.063W; AEC Qualified: Y; VDC_V: 50V; AEC Category: Q200; AEC Grade: 0
R141 R147 = CMP-0022599-4: RES, 7.15 k, 1%, 0.1 W, AEC-Q200 Grade 0, 0603; Manufacturer: Vishay-Dale; Power_W: 100mW; TempCo: 100 ppm/C; Value_Code: 7k15; Value: 7.15k; EIA_Code: E96; SizeX_mm: 1.6; SizeY_mm: 0.8; SizeZ_mm: 1; Value2: 0.1W; SizeArea_mm2: 1.28; AEC Qualified: Y; VDC_V: 75V; AEC Category: Q200; AEC Grade: 0
R156 = CMP-0021998-4: RES, 10.0 k, 1%, 0.1 W, AEC-Q200 Grade 0, 0603; Manufacturer: Vishay-Dale; Power_W: 100mW; TempCo: 100 ppm/C; Value_Code: 10k0; Value: 10.0k; EIA_Code: E96; Res_ohm: 10k; SizeX_mm: 1.6; SizeY_mm: 0.8; SizeZ_mm: 1; Value2: 0.1W; SizeArea_mm2: 1.28; AEC Qualified: Y; VDC_V: 75V; AEC Category: Q200; AEC Grade: 0
R157 R158 = CMP-0018707-3: RES, 5.1, 5%, 0.25 W, AEC-Q200 Grade 0, 1206; Manufacturer: Vishay-Dale; Power_W: 250mW; TempCo: 200 ppm/C; Value_Code: 5R10; Value: 5.1; EIA_Code: E24; SizeX_mm: 3.2; SizeY_mm: 1.6; SizeZ_mm: 1.35; Value2: 0.25W; SizeArea_mm2: 5.12; AEC Qualified: Y; VDC_V: 200V; AEC Category: Q200; AEC Grade: 0
R159 R164 R166 R171 R172 = CMP-0086941-2: 10 mOhms ±1% 1W Chip Resistor 1206 (3216 Metric) Automotive AEC-Q200, Current Sense, Moisture Resistant Metal Element; Manufacturer: Bourns; AEC Qualified: Yes; TempCo: 50ppm/°C; AEC Grade: Grade 0; Res_ohm: 0.01; SizeZ_mm: 0.8mm
R160 R165 = CMP-0090612-1: PTC Thermistors 30Vdc 185mA 13ohms PTC Overcurrent; Manufacturer: TDK; AEC Qualified: Yes; VDC_V: 30V; Value: 13Ω; Tolerance_%: 25%; Max Current: 90mA; SizeZ_mm: 3.8mm; AEC Grade: Grade 1
R161-R163 R167-R169 R173-R175 = CMP-0018656-3: RES, 330 k, 5%, 0.25 W, AEC-Q200 Grade 0, 1206; Manufacturer: Vishay-Dale; Power_W: 250mW; TempCo: 200 ppm/C; Value: 330k; EIA_Code: E24; SizeX_mm: 3.2; SizeY_mm: 1.6; SizeZ_mm: 1.35; Value2: 0.25W; SizeArea_mm2: 5.12; AEC Qualified: Y; VDC_V: 200V; AEC Category: Q200; AEC Grade: 0
R170 = CMP-0090617-1: 820V 10kA Varistor 1 Circuit Through Hole Disc 20mm; Manufacturer: Littelfuse; Varistor Voltage: 738V; TaMax_C: +125°C; ValueDisplayed: 350pF; Clamping Voltage: 1355V; AEC Qualified: Yes; Vc: 100A; TaMin_C: -40°C; AEC Grade: Grade 1; VDC_V: 670V; SizeZ_mm: 28mm
TP5 TP6 = CMP-0055138-1: Test Point, Miniature, Black, TH; Manufacturer: Keystone; CNHeader: FALSE; Green_Lifecycle: Active; Green_REACh: Passed; ContactFinish: Silver; CT: TRUE
TP7 TP8 = CMP-0055137-1: Test Point, Miniature, Red, TH; Manufacturer: Keystone; CNHeader: FALSE; Green_Lifecycle: Active; Green_REACh: Passed; ContactFinish: Silver; CT: TRUE
U43 U44 U46 = CMP-0077859-1: Automotive Qualified Precision, Zero-Crossover, 20MHz, 0.9pA Ib, RRIO, CMOS Operational Amplifier, DBV0005A (SOT-23-5); Alternate PartNumber: OPA320AQDBVTQ1; Alternate Manufacturer: Texas Instruments; SizeAreaWB_mm2: 14.82; SizeZ_mm: 1.45; SizeX_mm: 2.8; SizeY_mm: 2.9; SizeArea_mm2: 8.12; CompType: IC; AEC Qualified: Y; AEC Category: Q200
U45 U47 = CMP-0090912-1: Current Sensor 40A 1 Channel Hall Effect, Differential Bidirectional 16-SOIC (0.295", 7.50mm Width); Manufacturer: Allegro Microsystems; TJmax_C: +165°C; Coil Resistance: 1mΩ; Current Sensitivity: 33mV/A; Standoff Height: 0.1mm; TaMin_C: -40°C; Sensor Output: Analog Voltage; AEC Qualified: Yes; SizeZ_mm: 2.65mm; Operating Supply Current: 20mA; Max Supply Voltage: 3.46V; TaMax_C: +125°C; AEC Grade: Grade 1; Min Supply Voltage: 3.14V

## Sheet PMP22650 PFC GaN PH1.SchDoc
size 431 x 279 mm; DocumentNumber: 5; SheetNumber: 5; SheetTotal: 16; PageSetup: Record=PageOptions¦CenterHorizontal=True¦CenterVertical=True¦PrintScale=0.69¦XCorrection=1.00¦YCorrection=1.00¦PrintKind=0¦BorderSize=5000000¦LeftOffset=0¦BottomOffset=0¦Orientation=2¦PaperLength=1000¦PaperWidth=1000¦Scale=100¦PaperSource=15¦PrintQuality=600¦MediaType=1¦DitherType=10¦PaperKind=Letter¦PrintScaleMode=1
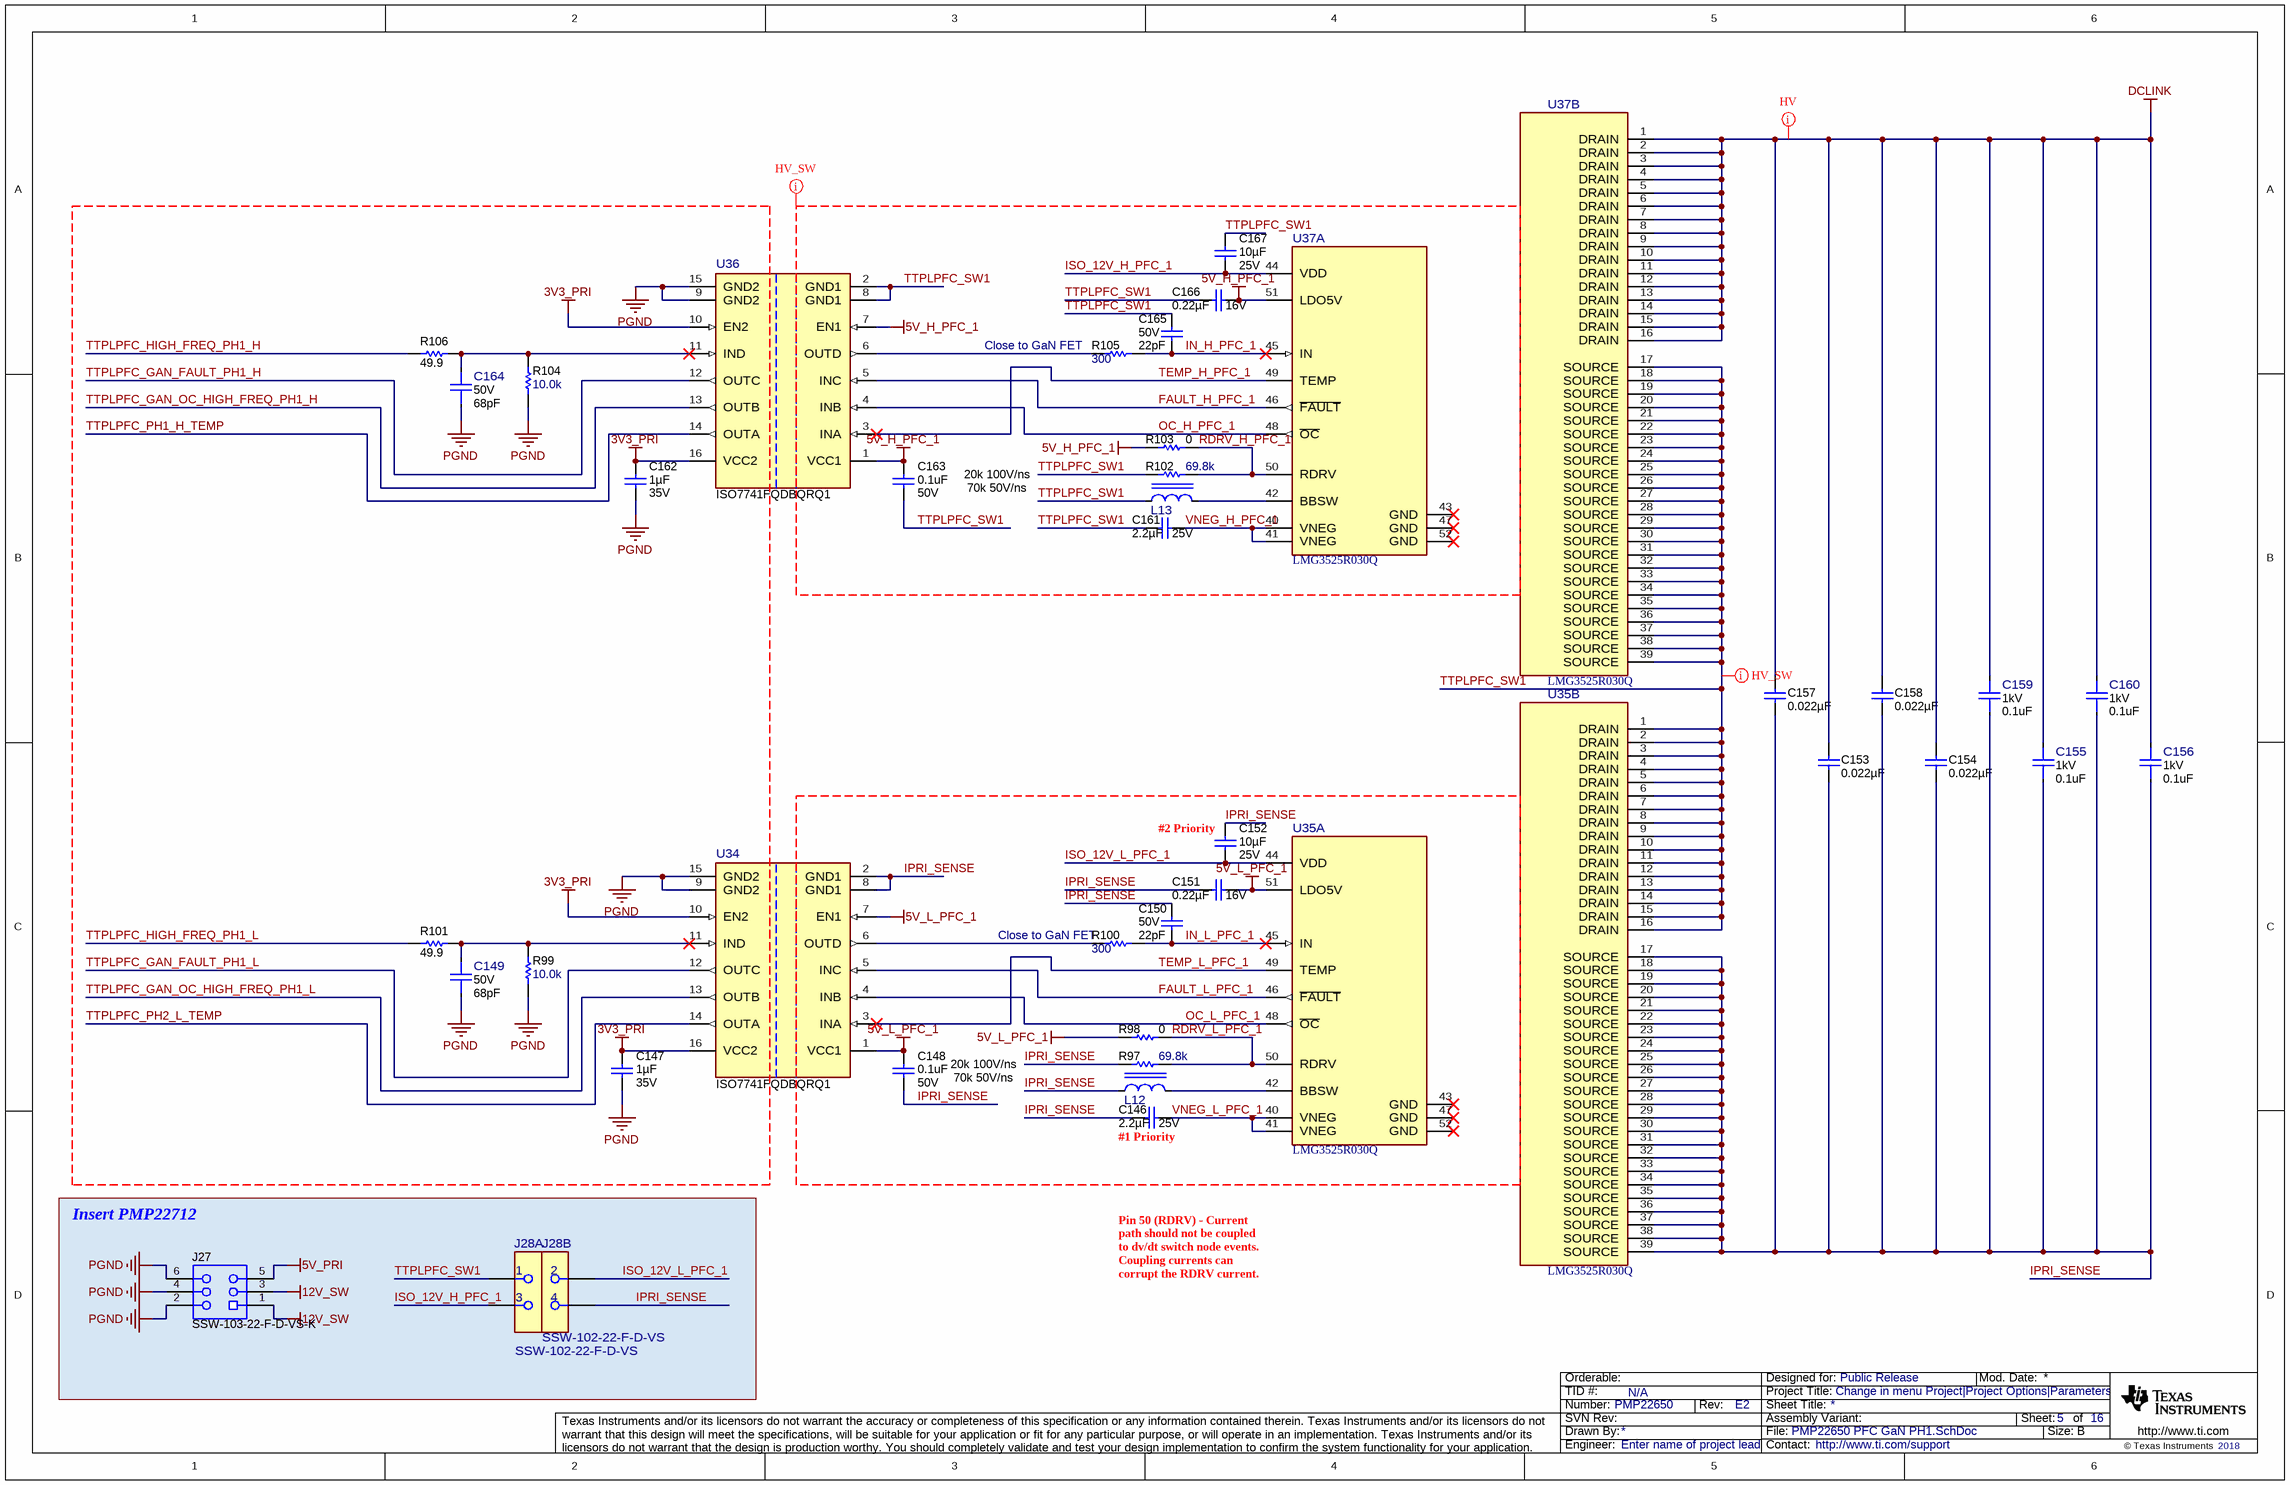
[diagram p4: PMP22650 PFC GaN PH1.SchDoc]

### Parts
C146  Cap_F: 2.2µF  VDC_V: 25V  [0805_HV]  (hidden comment: CGA4J3X7R1E225K125AB)
C147  VDC_V: 35V  ValueDisplayed: 1µF  [0402]  (hidden comment: GRT155R6YA105KE13D)
C148  VDC_V: 50V  ValueDisplayed: 0.1uF  [0402]  (hidden comment: GCM155R71H104KE02D)
C149  VDC_V: 50V  ValueDisplayed: 68pF  [FP-GCM1555C1H680JA16D_0402-MFG]  (hidden comment: GCM1555C1H680JA16D)
C150  VDC_V: 50V  ValueDisplayed: 22pF  [0402]  (hidden comment: GCM1555C1H220JA16D)
C151  VDC_V: 16V  ValueDisplayed: 0.22µF  [0402]  (hidden comment: GCM155R71C224KE02D)
C152  VDC_V: 25V  ValueDisplayed: 10µF  [1206_180]  (hidden comment: TMK316AB7106KLHT)
C153  ValueDisplayed: 0.022µF  [1206_190]  (hidden comment: C1206C223KDRACTU)
C154  ValueDisplayed: 0.022µF  [1206_190]  (hidden comment: C1206C223KDRACTU)
C155  VDC_V: 1kV  ValueDisplayed: 0.1uF  [FP-C1812X104KDRACAUTO_1812-MFG]  (hidden comment: C1812X104KDRACAUTO)
C156  VDC_V: 1kV  ValueDisplayed: 0.1uF  [FP-C1812X104KDRACAUTO_1812-MFG]  (hidden comment: C1812X104KDRACAUTO)
C157  ValueDisplayed: 0.022µF  [1206_190]  (hidden comment: C1206C223KDRACTU)
C158  ValueDisplayed: 0.022µF  [1206_190]  (hidden comment: C1206C223KDRACTU)
C159  VDC_V: 1kV  ValueDisplayed: 0.1uF  [FP-C1812X104KDRACAUTO_1812-MFG]  (hidden comment: C1812X104KDRACAUTO)
C160  VDC_V: 1kV  ValueDisplayed: 0.1uF  [FP-C1812X104KDRACAUTO_1812-MFG]  (hidden comment: C1812X104KDRACAUTO)
C161  Cap_F: 2.2µF  VDC_V: 25V  [0805_HV]  (hidden comment: CGA4J3X7R1E225K125AB)
C162  VDC_V: 35V  ValueDisplayed: 1µF  [0402]  (hidden comment: GRT155R6YA105KE13D)
C163  VDC_V: 50V  ValueDisplayed: 0.1uF  [0402]  (hidden comment: GCM155R71H104KE02D)
C164  VDC_V: 50V  ValueDisplayed: 68pF  [FP-GCM1555C1H680JA16D_0402-MFG]  (hidden comment: GCM1555C1H680JA16D)
C165  VDC_V: 50V  ValueDisplayed: 22pF  [0402]  (hidden comment: GCM1555C1H220JA16D)
C166  VDC_V: 16V  ValueDisplayed: 0.22µF  [0402]  (hidden comment: GCM155R71C224KE02D)
C167  VDC_V: 25V  ValueDisplayed: 10µF  [1206_180]  (hidden comment: TMK316AB7106KLHT)
J27  SSW-103-22-F-D-VS-K  [SAMTEC_SSW-103-22-F-D-VS-K]
J28  SSW-102-22-F-D-VS  [FP-SSW-102-22-F-D-VS_RCPT4-MFG]  (parts A,B of 2)
L12  MPIA2510V2-4R7-R  [FP-MPIA2510V2-4R7-R_1008-MFG]  (value not drawn)
L13  MPIA2510V2-4R7-R  [FP-MPIA2510V2-4R7-R_1008-MFG]  (value not drawn)
R97  ValueDisplayed: 69.8k  [0402]  (hidden comment: CRCW040269K8FKED)
R98  ValueDisplayed: 0  [0402]  (hidden comment: ERJ-2GE0R00X)
R99  ValueDisplayed: 10.0k  [0402]  (hidden comment: CRCW040210K0FKED)
R100  ValueDisplayed: 300  [0402]  (hidden comment: CRCW0402300RJNED)
R101  ValueDisplayed: 49.9  [0402]  (hidden comment: CRCW040249R9FKED)
R102  ValueDisplayed: 69.8k  [0402]  (hidden comment: CRCW040269K8FKED)
R103  ValueDisplayed: 0  [0402]  (hidden comment: ERJ-2GE0R00X)
R104  ValueDisplayed: 10.0k  [0402]  (hidden comment: CRCW040210K0FKED)
R105  ValueDisplayed: 300  [0402]  (hidden comment: CRCW0402300RJNED)
R106  ValueDisplayed: 49.9  [0402]  (hidden comment: CRCW040249R9FKED)
U34  ISO7741FQDBQRQ1  [DBQ0016A-MFG]
U35  LMG3525R030Q  [RQS0052A-MFG]  (parts A,B of 2)
U36  ISO7741FQDBQRQ1  [DBQ0016A-MFG]
U37  LMG3525R030Q  [RQS0052A-MFG]  (parts A,B of 2)

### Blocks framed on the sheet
Insert PMP22712: J27 J28

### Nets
3V3_PRI: C147.1 C162.1 U34.10(EN2) U34.16(VCC2) U36.10(EN2) U36.16(VCC2)
5V_H_PFC_1: C163.1 C166.1 R103.2 U36.1(VCC1) U36.7(EN1) U37.51(LDO5V)
5V_L_PFC_1: C148.1 C151.1 R98.2 U34.1(VCC1) U34.7(EN1) U35.51(LDO5V)
5V_PRI: J27.5
12V_SW: J27.1 J27.3
DCLINK: C153.1 C154.1 C155.2 C156.2 C157.1 C158.1 C159.2 C160.2 U37.1(DRAIN) U37.2(DRAIN) U37.3(DRAIN) U37.4(DRAIN) U37.5(DRAIN) U37.6(DRAIN) U37.7(DRAIN) U37.8(DRAIN) U37.9(DRAIN) U37.10(DRAIN) U37.11(DRAIN) U37.12(DRAIN) U37.13(DRAIN) U37.14(DRAIN) U37.15(DRAIN) U37.16(DRAIN)
PGND: C147.2 C149.1 C162.2 C164.1 J27.2 J27.4 J27.6 R99.1 R104.1 U34.9(GND2) U34.15(GND2) U36.9(GND2) U36.15(GND2)
FAULT_H_PFC_1: U36.5(INC) U37.46(~{FAULT})
FAULT_L_PFC_1: U34.5(INC) U35.46(~{FAULT})
IN_H_PFC_1: C165.2 R105.2 U37.45(IN)
IN_L_PFC_1: C150.2 R100.2 U35.45(IN)
IPRI_SENSE: C146.1 C148.2 C150.1 C151.2 C152.2 C153.2 C154.2 C155.1 C156.1 C157.2 C158.2 C159.1 C160.1 J28.4 L12.1 R97.1 U34.2(GND1) U34.8(GND1) U35.17(SOURCE) U35.18(SOURCE) U35.19(SOURCE) U35.20(SOURCE) U35.21(SOURCE) U35.22(SOURCE) U35.23(SOURCE) U35.24(SOURCE) U35.25(SOURCE) U35.26(SOURCE) U35.27(SOURCE) U35.28(SOURCE) U35.29(SOURCE) U35.30(SOURCE) U35.31(SOURCE) U35.32(SOURCE) U35.33(SOURCE) U35.34(SOURCE) U35.35(SOURCE) U35.36(SOURCE) U35.37(SOURCE) U35.38(SOURCE) U35.39(SOURCE)
ISO_12V_H_PFC_1: C167.1 J28.3 U37.44(VDD)
ISO_12V_L_PFC_1: C152.1 J28.2 U35.44(VDD)
OC_H_PFC_1: U36.4(INB) U37.48(~{OC})
OC_L_PFC_1: U34.4(INB) U35.48(~{OC})
RDRV_H_PFC_1: R102.2 R103.1 U37.50(RDRV)
RDRV_L_PFC_1: R97.2 R98.1 U35.50(RDRV)
TEMP_H_PFC_1: U36.3(INA) U37.49(TEMP)
TEMP_L_PFC_1: U34.3(INA) U35.49(TEMP)
TTPLPFC_GAN_FAULT_PH1_H: U36.12(OUTC)
TTPLPFC_GAN_FAULT_PH1_L: U34.12(OUTC)
TTPLPFC_GAN_OC_HIGH_FREQ_PH1_H: U36.13(OUTB)
TTPLPFC_GAN_OC_HIGH_FREQ_PH1_L: U34.13(OUTB)
TTPLPFC_HIGH_FREQ_PH1_H: R106.1
TTPLPFC_HIGH_FREQ_PH1_L: R101.1
TTPLPFC_PH1_H_TEMP: U36.14(OUTA)
TTPLPFC_PH2_L_TEMP: U34.14(OUTA)
TTPLPFC_SW1: C161.1 C163.2 C165.1 C166.2 C167.2 J28.1 L13.1 R102.1 U35.1(DRAIN) U35.2(DRAIN) U35.3(DRAIN) U35.4(DRAIN) U35.5(DRAIN) U35.6(DRAIN) U35.7(DRAIN) U35.8(DRAIN) U35.9(DRAIN) U35.10(DRAIN) U35.11(DRAIN) U35.12(DRAIN) U35.13(DRAIN) U35.14(DRAIN) U35.15(DRAIN) U35.16(DRAIN) U36.2(GND1) U36.8(GND1) U37.17(SOURCE) U37.18(SOURCE) U37.19(SOURCE) U37.20(SOURCE) U37.21(SOURCE) U37.22(SOURCE) U37.23(SOURCE) U37.24(SOURCE) U37.25(SOURCE) U37.26(SOURCE) U37.27(SOURCE) U37.28(SOURCE) U37.29(SOURCE) U37.30(SOURCE) U37.31(SOURCE) U37.32(SOURCE) U37.33(SOURCE) U37.34(SOURCE) U37.35(SOURCE) U37.36(SOURCE) U37.37(SOURCE) U37.38(SOURCE) U37.39(SOURCE)
VNEG_H_PFC_1: C161.2 U37.40(VNEG) U37.41(VNEG)
VNEG_L_PFC_1: C146.2 U35.40(VNEG) U35.41(VNEG)
NetC149_2: C149.2 R99.2 R101.2 U34.11(IND)
NetC164_2: C164.2 R104.2 R106.2 U36.11(IND)
NetL12_2: L12.2 U35.42(BBSW)
NetL13_2: L13.2 U37.42(BBSW)
NetR100_1: R100.1 U34.6(OUTD)
NetR105_1: R105.1 U36.6(OUTD)

Not connected (* = marked no-connect by the designer): U35 43(GND)* 47(GND)* 52(GND)*; U37 43(GND)* 47(GND)* 52(GND)*

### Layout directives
net class HV_SW: 5V_H_PFC_1, FAULT_H_PFC_1, IN_H_PFC_1, ISO_12V_H_PFC_1, OC_H_PFC_1, RDRV_H_PFC_1, TEMP_H_PFC_1, TTPLPFC_SW1, VNEG_H_PFC_1
net class HV: DCLINK

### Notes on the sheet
- (near R105) Close to GaN FET
- 20k 100V/ns
- 70k 50V/ns
- (near C152) #2 Priority
- (near R100) Close to GaN FET
- (near C148) 20k 100V/ns
- (near C148) 70k 50V/ns
- (near C146) #1 Priority
- Pin 50 (RDRV) - Current path should not be coupled to dv/dt switch node events. Coupling currents can corrupt the RDRV current.

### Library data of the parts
C146 C161 = CMP-0007975-2: CAP, CERM, 2.2 uF, 25 V, +/- 10%, X7R, AEC-Q200 Grade 1, 0805; Manufacturer: TDK; TaMin_C: -55°C; Polarized: N; SizeAreaWB_mm2: 6.75; Value1: Unknown; U/M: EA; Value: 2.2uF; TaMax_C: 125°C; SizeZ_mm: 1.45; SizeX_mm: 2; SizeY_mm: 1.25; Cap_Case: 0805; SizeArea_mm2: 2.5; AEC Qualified: Y; AEC Grade: 1; AEC Category: Q200
C147 C162 = CMP-0750099-1: CAP, CERM, 1 µF, 35 V,+/- 10%, X5R, AEC-Q200 Grade 3, 0402; Manufacturer: MuRata; AEC Grade: 3; AEC Category: Q200; Value: 1uF; SizeArea_mm2: 0.5; SizeZ_mm: 0.6; AEC Qualified: Y; TaMin_C: -55°C; SizeX_mm: 1; U/M: EA; Polarized: N; TaMax_C: 85°C
C148 C163 = CMP-0006356-2: CAP, CERM, 0.1 uF, 50 V, +/- 10%, X7R, AEC-Q200 Grade 1, 0402; Manufacturer: MuRata; TaMin_C: -55°C; Polarized: N; SizeAreaWB_mm2: 3; Value1: Unknown; U/M: EA; Value: 0.1uF; TaMax_C: 125°C; SizeZ_mm: 0.6; SizeX_mm: 1; SizeY_mm: 0.5; AEC Qualified: Y; Cap_F: 100nF; AEC Category: Q200
C149 C164 = CMP-0090521-1: 68pF ±5% 50V Ceramic Capacitor C0G, NP0 0402 (1005 Metric); Manufacturer: Murata; AEC Qualified: Yes; AEC Grade: Grade 1; TempCo: 30ppm/°C; SizeZ_mm: 0.55mm
C150 C165 = CMP-0006348-2: CAP, CERM, 22 pF, 50 V, +/- 5%, C0G/NP0, AEC-Q200 Grade 1, 0402; Manufacturer: MuRata; TaMin_C: -55°C; Polarized: N; SizeAreaWB_mm2: 3; Value1: Unknown; U/M: EA; Value: 22pF; TaMax_C: 125°C; SizeZ_mm: 0.6; SizeX_mm: 1; SizeY_mm: 0.5; AEC Qualified: Y; AEC Category: Q200
C151 C166 = CMP-0078265-1: CAP, CERM, 0.22 µF, 16 V,+/- 10%, X7R, AEC-Q200 Grade 1, 0402; Manufacturer: MuRata; TaMin_C: -55°C; Polarized: N; SizeAreaWB_mm2: 3; U/M: EA; Value: 0.22uF; TaMax_C: 125°C; SizeZ_mm: 0.6; SizeX_mm: 1; SizeY_mm: 0.5; AEC Qualified: Y; Cap_F: 220nF; AEC Category: Q200
C152 C167 = CMP-0750154-1: CAP, CERM, 10 µF, 25 V,+/- 10%, X7R, AEC-Q200 Grade 1, 1206; Manufacturer: Taiyo Yuden; AEC Qualified: Y; SizeZ_mm: 1.8; TaMax_C: 125°C; TaMin_C: -55°C; Cap_Case: 1206; Polarized: N; AEC Grade: 1; SizeY_mm: 1.6; Value: 10uF; SizeX_mm: 3.2; SizeAreaWB_mm2: 10.92; AEC Category: Q200; U/M: EA; SizeArea_mm2: 5.12
C153 C154 C157 C158 = CMP-0084048-1: CAP, CERM, 0.022 µF, 1000 V,+/- 10%, X7R, AEC-Q200 Grade 1, 1206; Manufacturer: Kemet; Polarized: N; CompType: Capacitor; Value: 0.022uF; U/M: EA; Cap_F: 22nF; VDC_V: 1kV; Value2: 1000V; TaMin_C: -55°C; TaMax_C: 125°C; Cap_Case: 1206; SizeArea_mm2: 5.12; SizeAreaWB_mm2: 10.92; SizeX_mm: 3.2; SizeY_mm: 1.6; SizeZ_mm: 1.9; AEC Category: Q200; AEC Qualified: Y; AEC Grade: 1
C155 C156 C159 C160 = CMP-0090548-1: as C226 on sheet PMP22650 PFC Power Stage
J27 = CMP-0055666-1: Receptacle, 2.54mm, 3x2, Tin, SMT; Manufacturer: Samtec; CNHeader: FALSE; Current_A: 5.7A; Gender: Female; CompType: Socket Strip; Row_Count: 2; RowSpacing_mm: 2.54; ContactFinish: Gold; CT: TRUE; Cert_UL: Y
J28 = CMP-0090790-1: 4 Position Receptacle Connector  Surface Mount; Manufacturer: Samtec; DUT-Pitch_mm: 2.54mm; SizeZ_mm: 10.21mm; Current_A: 4.7A; ContactFinish: Gold,Nickel; Conn Gender: Female; Voltage_V: 655V; Is Female: yes; AEC Qualified: No; Row_Count: 2; Conn Orientation: Vertical; Standoff Height: 0.97mm
L12 L13 = CMP-0090507-1: 4.7µH Shielded Molded Inductor 1.22A 262mOhm Max 1008 (2520 Metric); Manufacturer: Eaton; Material: Metal Composite; Value: 4.7uH; Test Frequency: 1MHz; Isat: 1.8A; DCR_ohm: 0.262; AEC Grade: Grade 1; Tolerance_%: 20%; AEC Qualified: Yes; Self Resonant Frequency: 25MHz; SizeZ_mm: 1.05mm; Shrouded: true
R97 R102 = CMP-0026510-2: RES, 69.8 k, 1%, 0.063 W, AEC-Q200 Grade 0, 0402; Manufacturer: Vishay-Dale; Power_W: 63mW; TempCo: 100 ppm/C; Value_Code: 69k8; Value: 69.8k; EIA_Code: E96; SizeX_mm: 1; SizeY_mm: 0.5; SizeZ_mm: 0.6; Value2: 0.063W; AEC Qualified: Y; VDC_V: 50V; AEC Category: Q200; AEC Grade: 0
R98 R103 = CMP-0026992-3: RES, 0, 5%, 0.1 W, AEC-Q200 Grade 0, 0402; Manufacturer: Panasonic; Power_W: 100mW; TempCo: 600 ppm/C; Value_Code: 0000; Value: 0; EIA_Code: E24; SizeX_mm: 1; SizeY_mm: 0.5; SizeZ_mm: 0.6; Value2: 0.1W; AEC Qualified: Y; VDC_V: 50V; AEC Category: Q200; SizeAreaWB_mm2: 3
R99 R104 = CMP-0025958-3: as R131 on sheet PMP22650 PFC Power Stage
R100 R105 = CMP-0026902-3: RES, 300, 5%, 0.063 W, AEC-Q200 Grade 0, 0402; Manufacturer: Vishay-Dale; Power_W: 63mW; TempCo: 200 ppm/C; Value_Code: 300R; Value: 300; EIA_Code: E24; SizeX_mm: 1; SizeY_mm: 0.5; SizeZ_mm: 0.6; Value2: 0.063W; AEC Qualified: Y; VDC_V: 50V; AEC Category: Q200; AEC Grade: 0
R101 R106 = CMP-0026404-2: RES, 49.9, 1%, 0.063 W, AEC-Q200 Grade 0, 0402; Manufacturer: Vishay-Dale; Power_W: 63mW; TempCo: 100 ppm/C; Value_Code: 49R9; Value: 49.9; EIA_Code: E96; SizeX_mm: 1; SizeY_mm: 0.5; SizeZ_mm: 0.6; Value2: 0.063W; AEC Qualified: Y; VDC_V: 50V; AEC Category: Q200; AEC Grade: 0
U34 U36 = CMP-0090469-1: Manufacturer: Texas Instruments; TaMin_C: -40°C; TaMax_C: +125°C; TJmax_C: +150°C; AEC Grade: Grade 1; Min Supply Voltage: 2.25V; AEC Qualified: Yes; Max Supply Voltage: 5.5V; Standoff Height: 0.11mm; Nominal Supply Current: 1.5-18mA; SizeZ_mm: 1.75mm
U35 U37 = CMP-0089968-2: 650-V 30-mΩ GaN FET with Integrated Driver and Protection; Manufacturer: Texas Instruments; Output Voltage: 520V; Nominal Supply Current: 540uA; Min Supply Voltage: 7.5V; Standoff Height: 0mm; AEC Grade: Grade 1; Max Supply Voltage: 18V; Number Of Outputs: 1; AEC Qualified: Yes; TJmax_C: +125°C; SizeZ_mm: 1mm; AEC Category: Q200; CompType: IC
